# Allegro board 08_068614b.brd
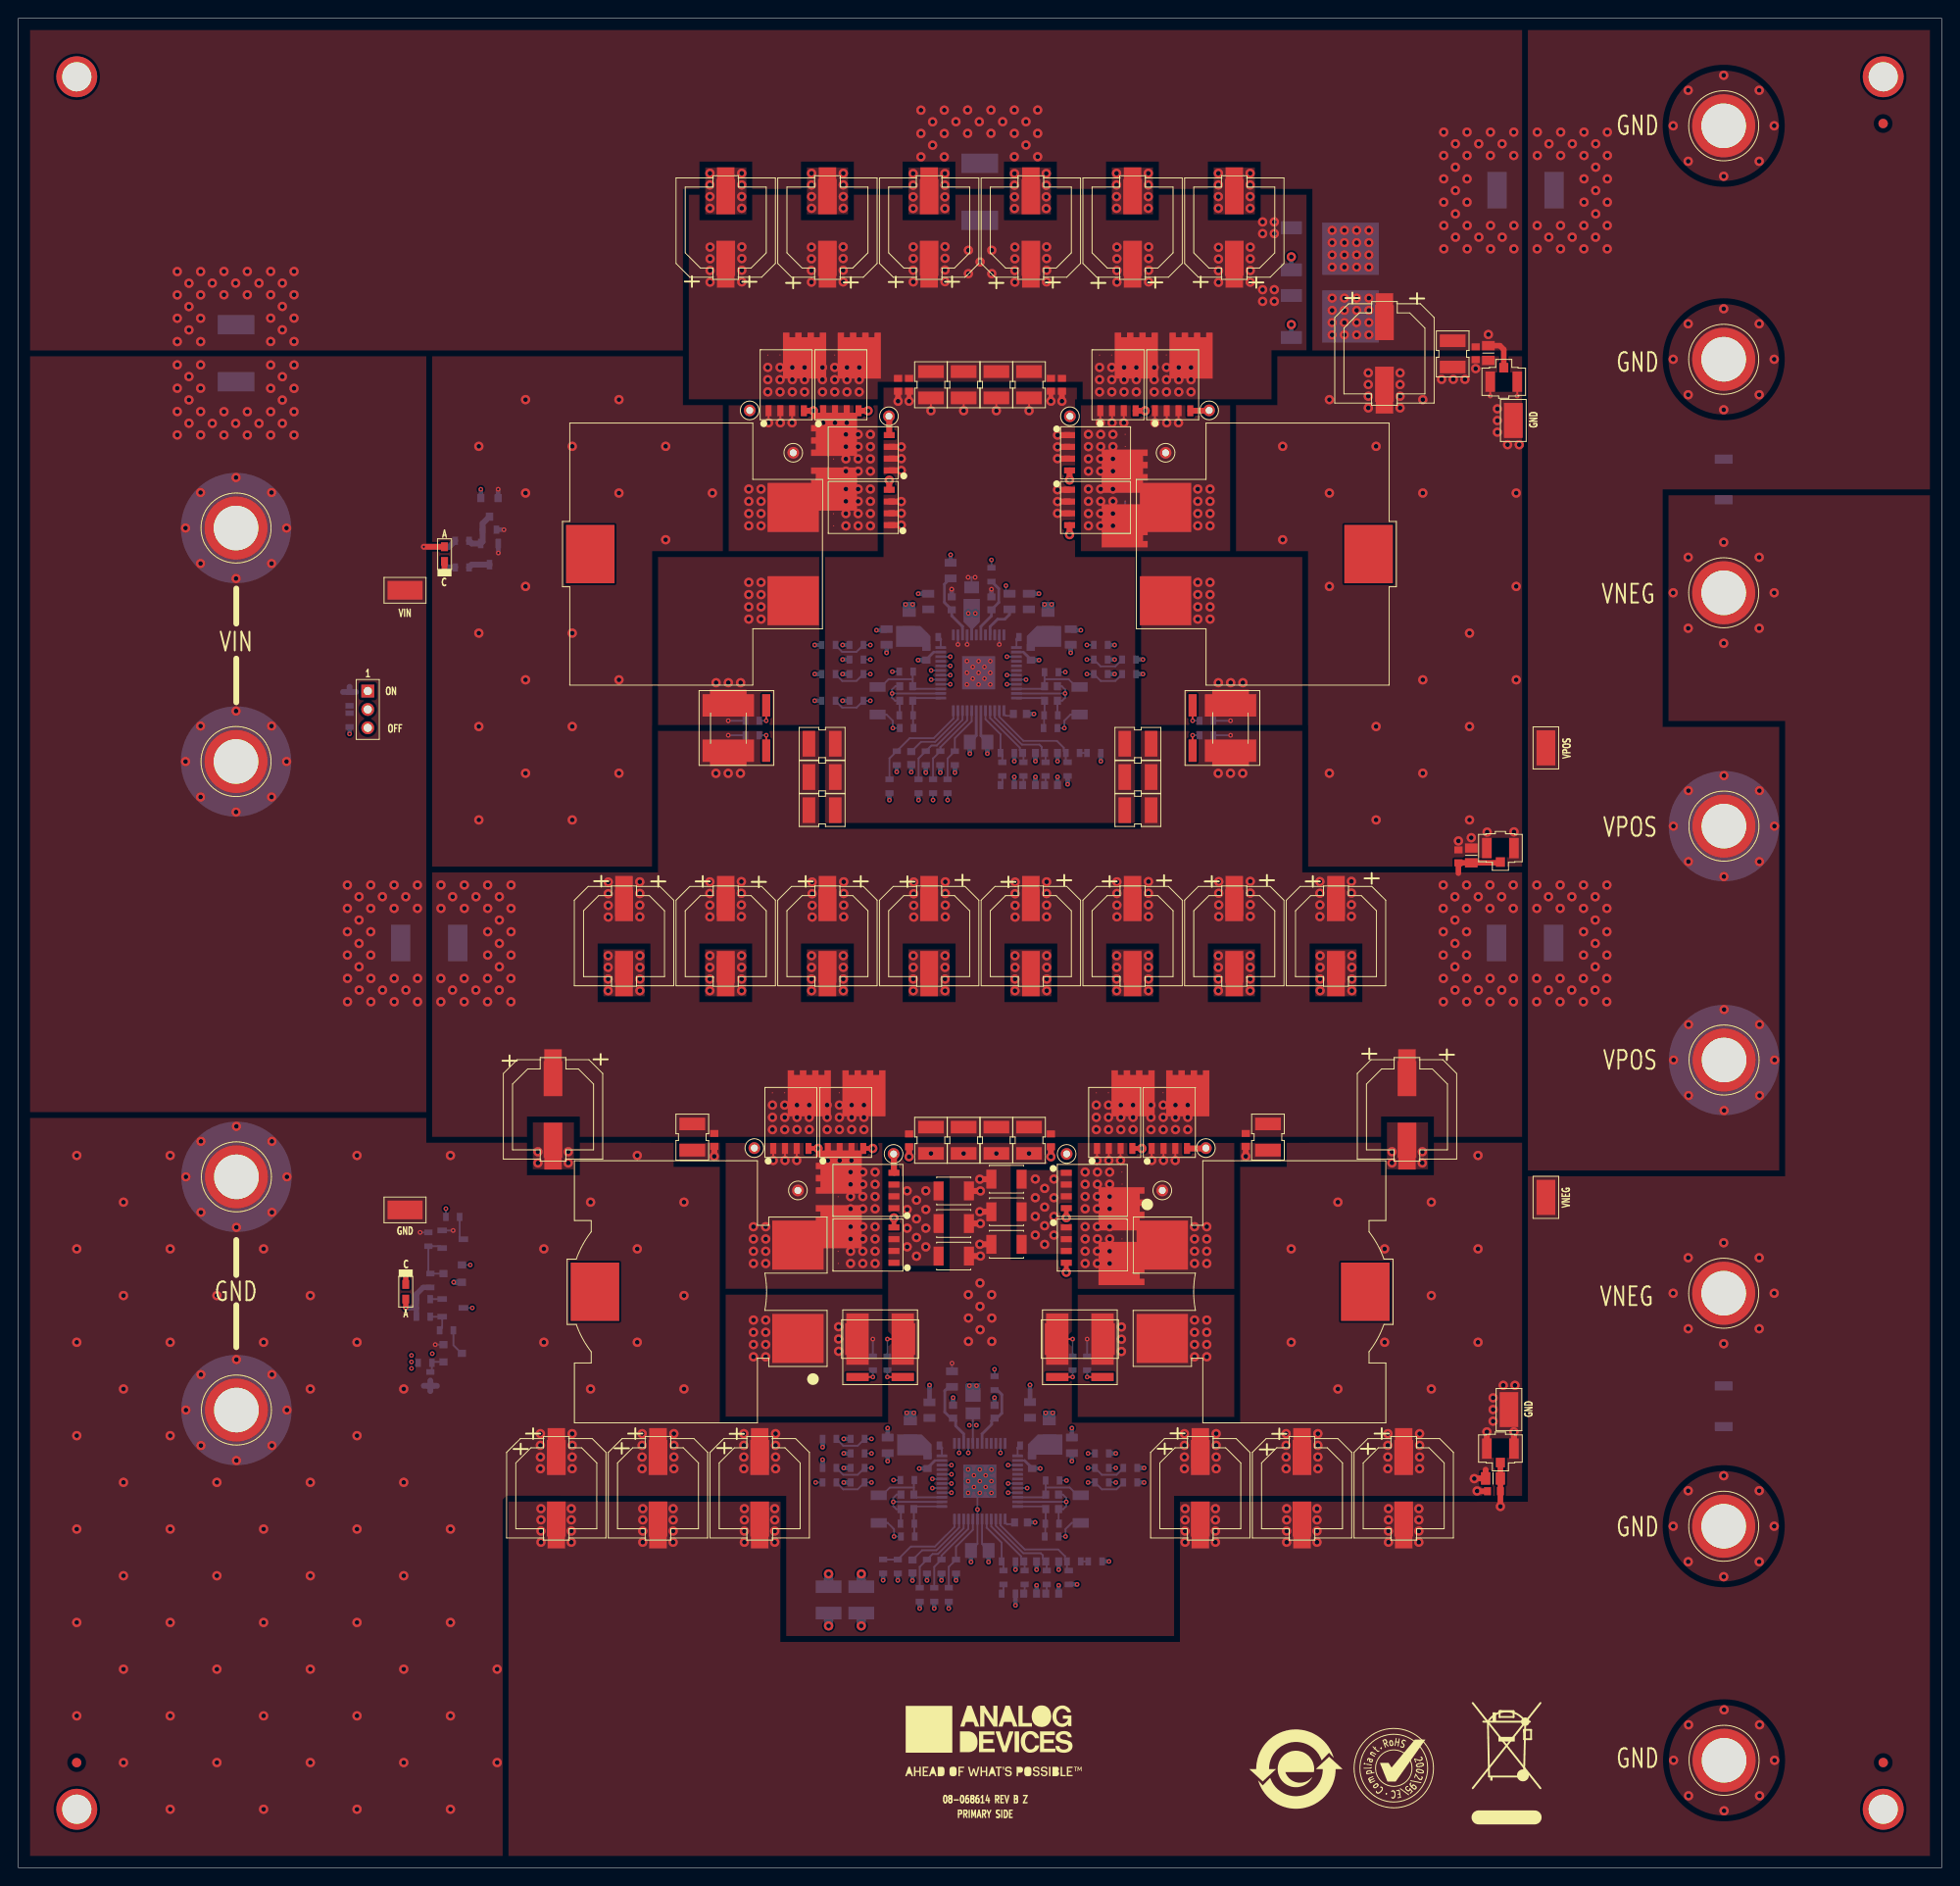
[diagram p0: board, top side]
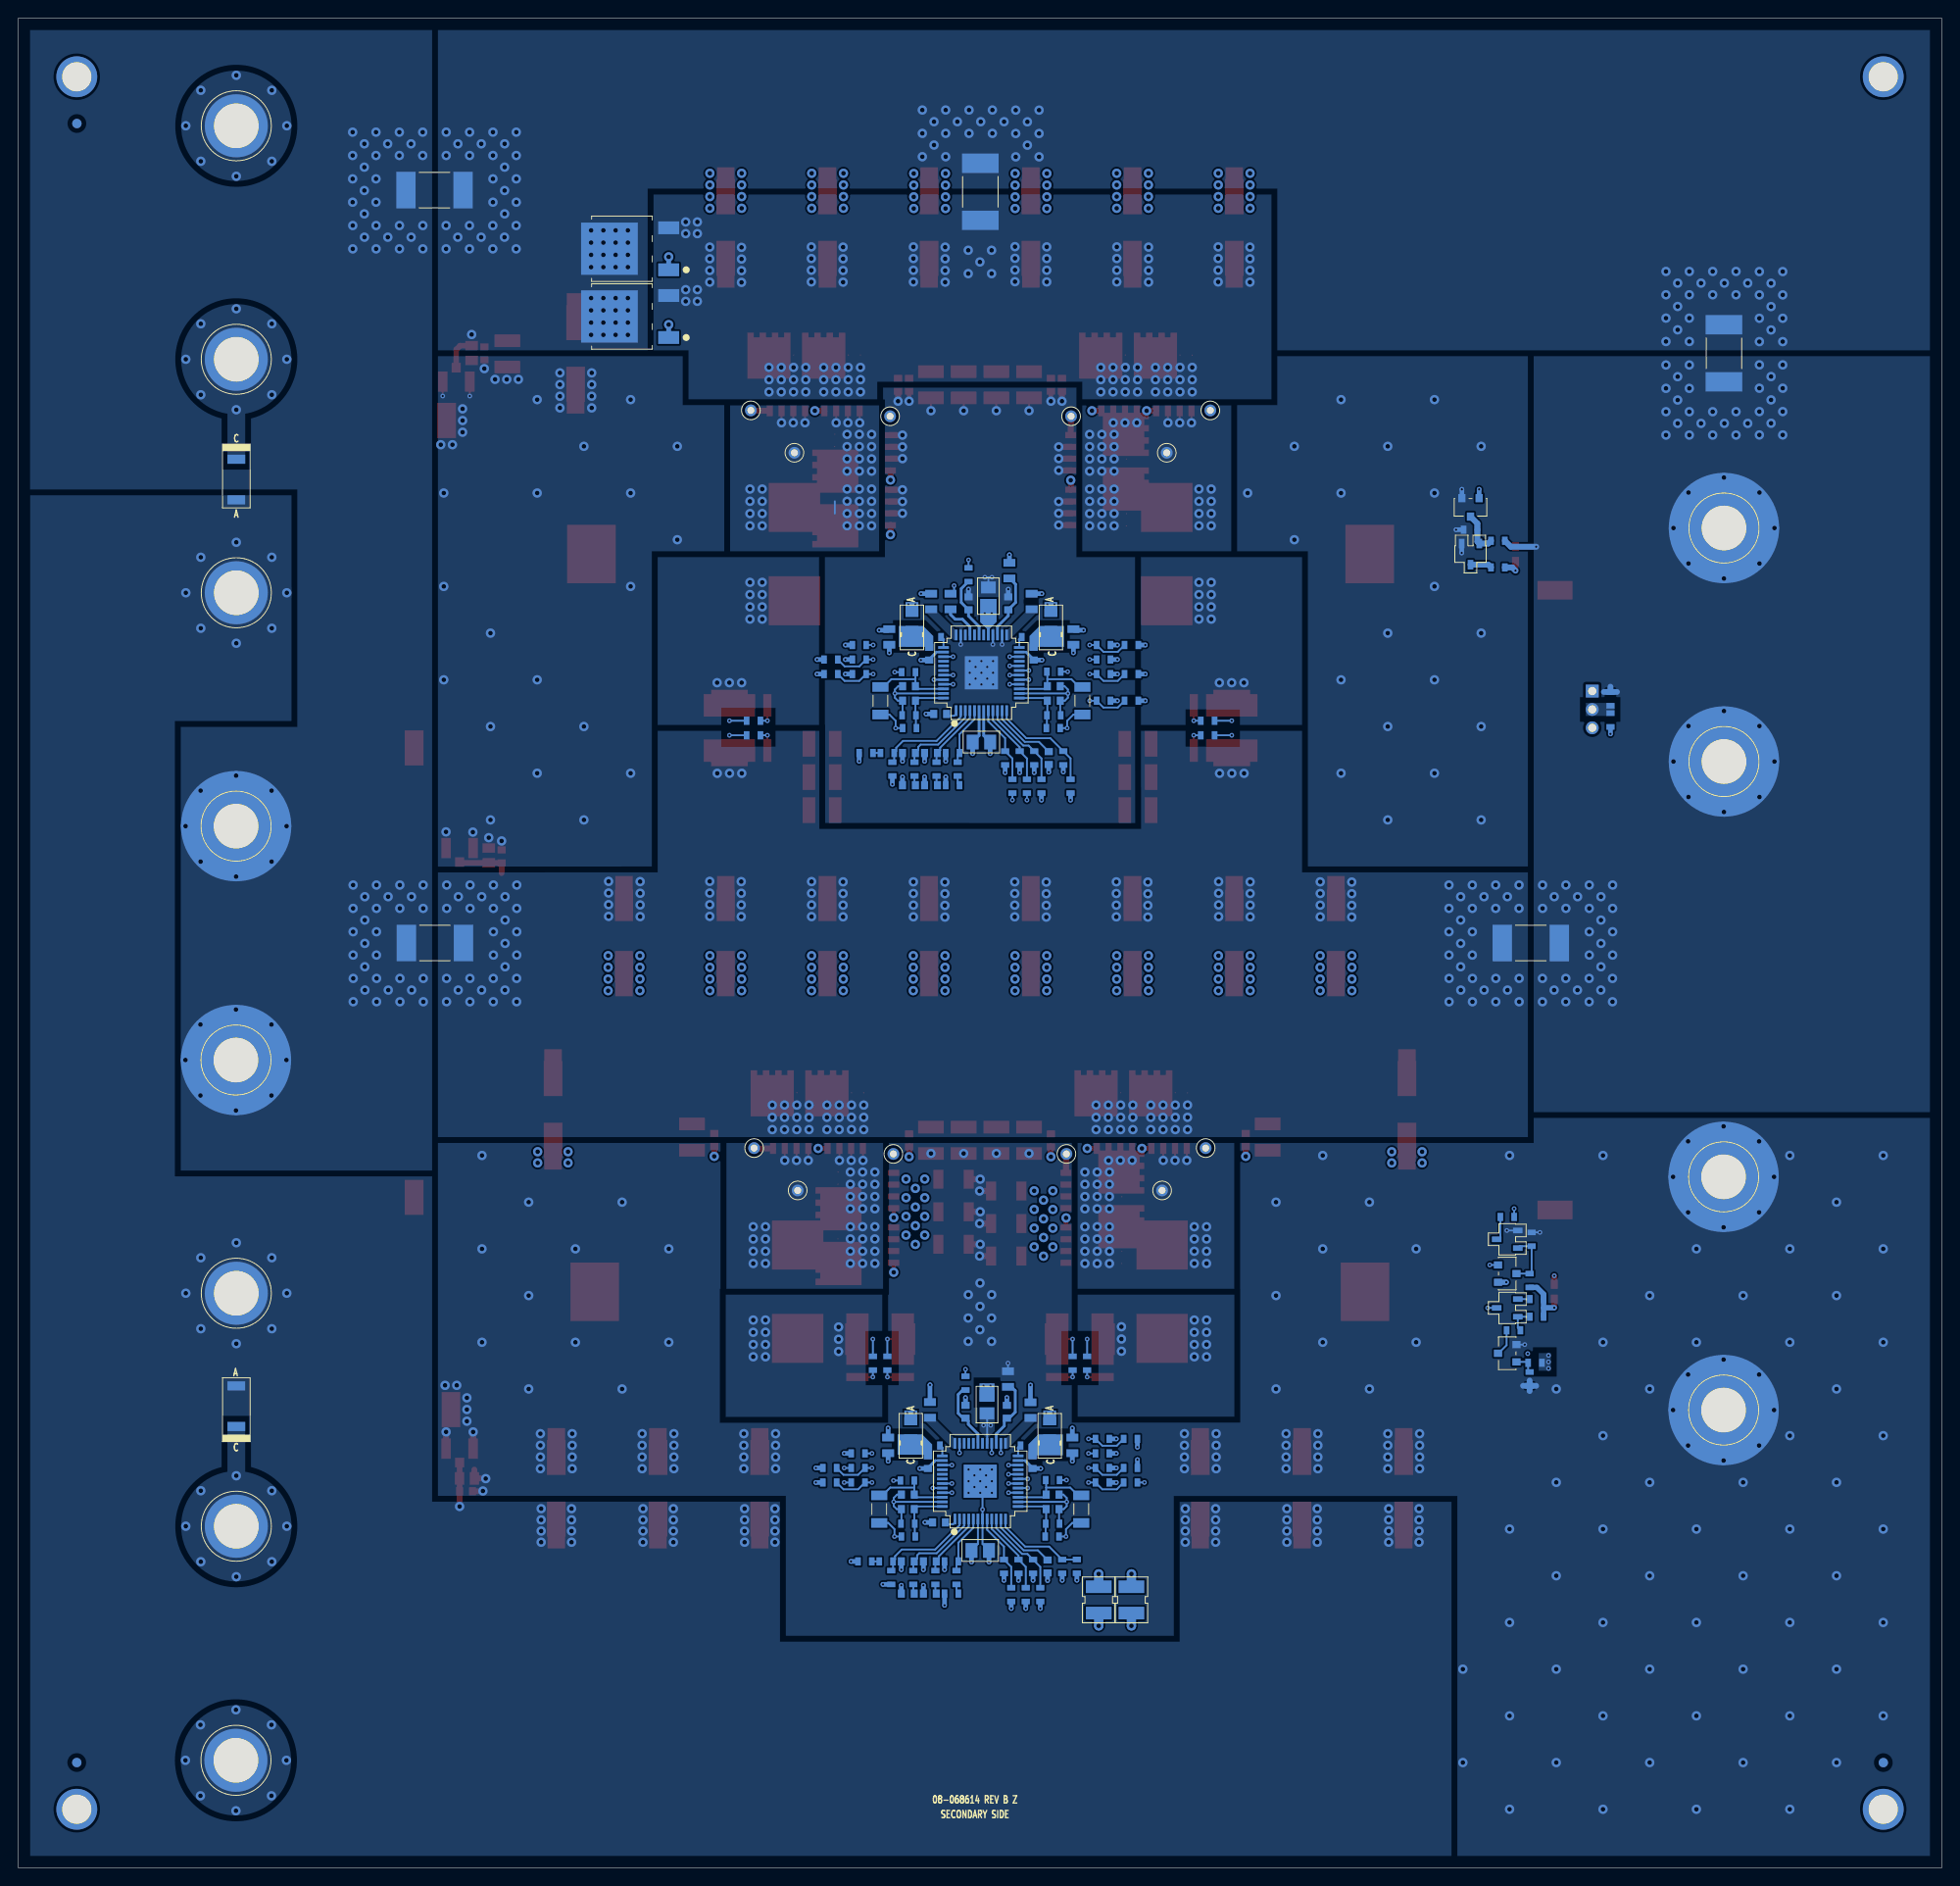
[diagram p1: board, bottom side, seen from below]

Outline 209.17 x 201.17 mm; copper layers: TOP, L2_PWR, L3_SIG, L4_SIG, L5_GND, BOTTOM. Coordinates in mm from the lower left corner of the outline.
Outline path: 0,201.17 0,0 209.17,0 209.17,201.17 0,201.17

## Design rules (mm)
constraint set DEFAULT: 

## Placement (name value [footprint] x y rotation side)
C1  0.1NF  [C0603]  109.91 121.25 0 bottom
C2  0.1uF  [C0603]  109.91 117.75 0 bottom
C3  47PF  [C0603]  112.31 121.25 0 bottom
C4  0.01uF  [C0603]  112.31 117.75 0 bottom
C5  10pF  [C0603]  97.11 120.7 90 bottom
C6  0.01uF  [C0603]  108.92 125.5 180 bottom
C7  4.7uF  [C0805H53]  103.67 138.31 270 bottom
C8  4.7uF  [C0805H53]  104.43 122.44 180 bottom
C9  0.1uF  [C0603]  105.83 137.53 270 bottom
C10  0.22uF  [C0603]  110.12 132.06 90 bottom
C11  0.22uF  [C0603]  98.75 132.06 90 bottom
C12  1uF  [C0603]  101.51 137.53 90 bottom
C13  120UF  [CPLSMSQ406H500]  99.05 178.42 90 top
C14  120UF  [CPLSMSQ406H500]  87.99 178.42 90 top
C15  120UF  [CPLSMSQ406H500]  110.12 178.42 90 top
C16  0.1uF  [C0603]  96.87 161.31 270 top
C17  120UF  [CPLSMSQ406H500]  121.18 178.42 90 top
C18  10UF  [C1210H110]  99.25 161.31 90 top
C19  0.1uF  [C0603]  112.3 161.31 270 top
C20  10UF  [C1210H110]  102.81 161.31 90 top
C21  0.1uF  [C0603]  95.67 161.31 90 top
C22  10UF  [C1210H110]  106.36 161.31 90 top
C23  10UF  [C1210H110]  109.92 161.31 90 top
C24  0.1uF  [C0603]  113.5 161.31 90 top
C25  0.1uF  [C0603]  96.56 126.94 0 bottom
C26  0.1uF  [C0603]  112.3 126.94 180 bottom
C27  0.1uF  [C0603]  96.56 128.52 0 bottom
C28  120UF  [CPLSMSQ406H500]  99.05 101.33 270 top
C29  0.1uF  [C0603]  112.3 128.52 180 bottom
C30  120UF  [CPLSMSQ406H500]  76.93 101.33 270 top
C31  120UF  [CPLSMSQ406H500]  121.18 101.33 270 top
C32  120UF  [CPLSMSQ406H500]  132.24 101.33 270 top
C33  120UF  [CPLSMSQ406H500]  143.3 101.33 270 top
C34  120UF  [CPLSMSQ406H500]  110.12 101.33 270 top
C35  120UF  [CPLSMSQ406H500]  65.87 101.33 270 top
C36  10UF  [C1210H110]  121.76 118.64 0 top
C37  10UF  [C1210H110]  87.41 122.26 180 top
C38  120UF  [CPLSMSQ406H500]  87.99 101.33 270 top
C39  0.015uF  [C0603]  156.62 110.01 270 top
C40  10UF  [C1210H110]  121.76 115.04 0 top
C41  10UF  [C1210H110]  87.41 118.64 180 top
C42  10UF  [C1210H110]  87.41 115.04 180 top
C43  120UF  [CPLSMSQ406H500]  148.57 164.72 270 top
C44  10UF  [C1210H110]  121.76 122.26 0 top
C45  0.1NF  [C0603]  110.04 33.31 0 bottom
C46  0.1uF  [C0603]  110.04 29.81 0 bottom
C47  33pF  [C0603]  112.44 33.31 0 bottom
C48  0.015uF  [C0603]  112.44 29.81 0 bottom
C49  10pF  [C0603]  97.24 32.76 90 bottom
C50  0.01uF  [C0603]  109.04 37.56 180 bottom
C51  4.7uF  [C0805H53]  103.82 50.37 270 bottom
C52  4.7uF  [C0805H53]  104.56 34.5 180 bottom
C53  0.1uF  [C0603]  106.16 49.59 270 bottom
C54  0.22uF  [C0603]  110.24 44.12 90 bottom
C55  0.22uF  [C0603]  98.88 44.12 90 bottom
C56  1uF  [C0603]  101.66 49.59 90 bottom
C57  100UF  [CPLSMSQ327H276]  65.87 101.33 270 top
C58  100UF  [CPLSMSQ327H276]  76.93 101.33 270 top
C59  100UF  [CPLSMSQ327H276]  87.99 101.33 270 top
C60  0.1uF  [C0603]  96.87 79.12 270 top
C61  100UF  [CPLSMSQ327H276]  99.05 101.33 270 top
C62  10UF  [C1210H110]  102.81 79.12 90 top
C63  0.1uF  [C0603]  133.49 79.16 270 top
C64  10UF  [C1210H110]  99.25 79.12 90 top
C65  0.1uF  [C0603]  75.68 79.16 90 top
C66  68UF  [CPLSMSQ406H500]  151.02 82.48 270 top
C67  0.1uF  [C0603]  112.3 79.12 90 top
C68  10UF  [C1210H110]  73.29 79.47 90 top
C69  0.47uF  [C0603]  96.69 39 0 bottom
C70  10UF  [C1210H110]  88.12 29.12 270 bottom
C71  0.47uF  [C0603]  112.43 39 180 bottom
C72  100UF  [CPLSMSQ327H276]  110.12 101.33 270 top
C73  100UF  [CPLSMSQ327H276]  121.18 101.33 270 top
C74  0.1uF  [C0603]  96.69 40.58 0 bottom
C75  100UF  [CPLSMSQ327H276]  132.24 101.33 270 top
C76  100UF  [CPLSMSQ327H276]  143.3 101.33 270 top
C77  0.1uF  [C0603]  112.43 40.58 180 bottom
C78  330UF  [CPLSMSQ406H500]  69.56 41.27 270 top
C79  330UF  [CPLSMSQ406H500]  80.63 41.27 270 top
C80  10UF  [C1210H110]  106.36 79.12 90 top
C81  330UF  [CPLSMSQ406H500]  58.5 41.27 270 top
C82  10UF  [C1210H110]  109.92 79.12 90 top
C83  330UF  [CPLSMSQ406H500]  150.67 41.27 270 top
C84  10uF  [C1210H106]  101.73 73.61 0 top
C85  330UF  [CPLSMSQ406H500]  139.61 41.27 270 top
C86  10uF  [C1210H106]  101.73 70.07 0 top
C87  68UF  [CPLSMSQ406H500]  58.15 82.48 270 top
C88  330UF  [CPLSMSQ406H500]  128.54 41.27 270 top
C89  10uF  [C1210H106]  101.73 66.53 0 top
C90  10uF  [C1210H106]  107.47 67.81 180 top
C91  10UF  [C1210H110]  135.9 79.47 90 top
C92  0.1uF  [C0603]  158.49 164.74 90 top
C93  10uF  [C1210H106]  107.47 71.35 180 top
C94  10UF  [C1210H110]  91.67 29.12 270 bottom
C95  10uF  [C1210H106]  107.47 74.89 180 top
C96  0.015uF  [C0603]  160.48 40.94 180 top
C97  120UF  [CPLSMSQ406H500]  76.93 178.42 90 top
C98  68UF  [CPLSMSQ327H461]  58.5 41.27 270 top
C99  120UF  [CPLSMSQ406H500]  132.24 178.42 90 top
C100  68UF  [CPLSMSQ327H461]  69.56 41.27 270 top
C101  68UF  [CPLSMSQ327H461]  58.15 82.48 270 top
C102  68UF  [CPLSMSQ327H461]  76.93 178.42 90 top
C103  68UF  [CPLSMSQ327H461]  151.02 82.48 270 top
C104  68UF  [CPLSMSQ327H461]  128.54 41.27 270 top
C105  68UF  [CPLSMSQ327H461]  87.99 178.42 90 top
C106  68UF  [CPLSMSQ327H461]  99.05 178.42 90 top
C107  68UF  [CPLSMSQ327H461]  139.61 41.27 270 top
C108  68UF  [CPLSMSQ327H461]  110.12 178.42 90 top
C109  68UF  [CPLSMSQ327H461]  150.67 41.27 270 top
C110  68UF  [CPLSMSQ327H461]  121.18 178.42 90 top
C111  68UF  [CPLSMSQ327H461]  80.63 41.27 270 top
C112  68UF  [CPLSMSQ327H461]  132.24 178.42 90 top
C113  68UF  [CPLSMSQ327H461]  148.57 164.72 270 top
C114  10UF  [C1210H110]  155.99 164.67 90 top
C115  0.015uF  [C0805]  159.87 164.76 90 top
C116  0.015uF  [C0805]  158.01 110.11 270 top
C117  0.015uF  [C0805]  160.38 42.34 180 top
D1  DFLS1100-7  [POWERDI123]  111.99 134.91 90 bottom
D2  DFLS1100-7  [POWERDI123]  96.88 134.91 90 bottom
D3  DFLS1100-7  [POWERDI123]  112.11 46.97 90 bottom
D4  DFLS1100-7  [POWERDI123]  97 46.97 90 bottom
D5  PMEG3050EP,115  [SOD128]  185.47 50.19 90 bottom
D6  PMEG3050EP,115  [SOD128]  185.47 151 270 bottom
DS1  TLMS1000GS08  [LED0603]  46.34 142.89 90 top
DS2  TLMS1000GS08  [LED0603]  42.13 62.64 270 top
J1  U.FL-R-SMT-1(01)  [CNHIROSE-U_FL-R-SMT-1]  161.55 161.65 180 top
J2  U.FL-R-SMT-1(01)  [CNHIROSE-U_FL-R-SMT-1]  161.18 110.91 0 top
J3  U.FL-R-SMT-1(01)  [CNHIROSE-U_FL-R-SMT-1]  161.18 45.59 0 top
L1  2.2UH  [L2815]  69.92 142.89 90 top
L2  2.2UH  [L2815]  139.12 142.89 270 top
L3  6.8UH  [LSML1102W764H728]  73.22 62.64 90 top
L4  6.8UH  [LSML1102W764H728]  135.97 62.65 270 top
NOREF  -  []  104.65 96.77 0 top
NOREF#2  -  []  171.13 21.59 0 top
NOREF#3  -  []  85.65 7.39 0 top
NOREF#4  -  []  138.94 10.72 0 top
NOREF#5  -  []  209.17 0 90 top
NOREF#6  -  []  0 201.17 0 top
NOREF#7  -  []  205.61 6.35 0 top
NOREF#8  -  []  10.82 307.1 0 top
NOREF#9  -  []  43.39 83.91 0 top
NOREF#10  -  []  104.83 225.4 0 top
NOREF#11  -  []  -50.8 -58.06 0 top
NOREF#12  -  []  0 0 0 top
NOREF#13  -  []  249 269.2 0 top
NOREF#14  -  []  188.64 37.14 0 top
NOREF#15  -  []  -50.8 -58.06 0 top
NOREF#16  -  []  209.17 0 90 top
NOREF#17  -  [unnamed#2]  6.35 6.35 0 top
NOREF#18  -  [unnamed#2]  6.35 194.82 0 top
NOREF#19  -  []  -50.8 -58.06 0 top
NOREF#20  -  []  9.07 14.72 0 top
NOREF#21  -  []  9.07 14.72 0 top
NOREF#22  -  []  149.59 10.82 0 top
NOREF#23  -  []  0 201.17 270 top
NOREF#24  -  []  106.07 13.77 0 top
NOREF#25  -  []  6.35 6.35 0 top
NOREF#26  -  []  -50.8 -58.06 0 top
NOREF#27  -  []  6.35 6.35 0 top
NOREF#28  -  [unnamed#2]  202.82 194.82 0 top
NOREF#29  -  []  0 0 0 top
NOREF#30  -  []  209.17 0 0 top
NOREF#31  -  [unnamed#2]  6.34 11.42 0 top
NOREF#32  -  [unnamed#2]  202.82 6.35 0 top
NOREF#33  -  []  209.17 201.17 180 top
NOREF#34  -  []  0 201.17 0 top
NOREF#35  -  [unnamed#2]  202.81 189.73 0 top
NOREF#36  -  []  0 0 0 top
NOREF#37  -  []  274.23 90.82 0 top
NOREF#38  -  [unnamed#2]  202.82 11.43 0 top
NOREF#39  -  [unnamed#2]  6.34 11.42 180 bottom
NOREF#40  -  [unnamed#2]  202.82 11.43 180 bottom
NOREF#41  -  [unnamed#2]  202.81 189.73 180 bottom
P1  KFH-032-10ET  [CNPEMKFH-032]  23.67 145.73 0 top
P2  KFH-032-10ET  [CNPEMKFH-032]  23.67 120.33 0 top
P3  KFH-032-10ET  [CNPEMKFH-032]  23.71 49.78 0 top
P4  KFH-032-10ET  [CNPEMKFH-032]  23.71 75.15 0 top
P5  62000311121  [CNTHMHDR1X3L236W79H244]  38 127.99 270 top
P6  KFH-032-10ET  [CNPEMKFH-032]  185.51 87.85 0 top
P7  KFH-032-10ET  [CNPEMKFH-032]  185.51 11.67 0 top
P8  KFH-032-10ET  [CNPEMKFH-032]  185.49 113.3 0 top
P9  KFH-032-10ET  [CNPEMKFH-032]  185.47 189.48 0 top
P12  KFH-032-10ET  [CNPEMKFH-032]  185.47 37.14 0 top
P13  KFH-032-10ET  [CNPEMKFH-032]  185.47 62.48 0 top
P14  KFH-032-10ET  [CNPEMKFH-032]  185.47 164.08 0 top
P15  KFH-032-10ET  [CNPEMKFH-032]  185.47 138.68 0 top
Q1  2N7002LT1G  [SOT23-M3]  51.24 147.97 0 bottom
Q2  SUD50P08-25L  [TO252-3]  142.64 168.74 90 bottom
Q3  SUD50P08-25L  [TO252-3]  142.64 176.11 90 bottom
Q4  DMN67D8L-7  [SOT23_B]  51.24 142.89 0 bottom
Q5  BSC032N04LSATMA1  [SON8]  83.51 161.31 0 top
Q6  BSC032N04LSATMA1  [SON8]  91.89 147.97 90 top
Q7  BSC032N04LSATMA1  [SON8]  119.59 161.31 0 top
Q8  BSC032N04LSATMA1  [SON8]  117.15 153.91 270 top
Q9  BSC032N04LSATMA1  [SON8]  89.45 161.31 0 top
Q10  BSC032N04LSATMA1  [SON8]  91.89 153.91 90 top
Q11  BSC032N04LSATMA1  [SON8]  125.54 161.31 0 top
Q12  BSC032N04LSATMA1  [SON8]  117.15 147.97 270 top
Q13  2N7002LT1G  [SOT23-M3]  47.24 55.95 90 bottom
Q14  DMP610DL  [SOT23_B]  47.24 60.89 90 bottom
Q15  2N7002LT1G  [SOT23-M3]  47.24 64.62 270 bottom
Q16  DMN67D8L-7  [SOT23_B]  47.24 68.35 90 bottom
Q17  BSC065N06LS5ATMA1  [SON8]  89.96 81.06 0 top
Q18  BSC027N06LS5ATMA1  [SON8]  92.4 73.67 90 top
Q19  BSC065N06LS5ATMA1  [SON8]  119.23 81.06 0 top
Q20  BSC027N06LS5ATMA1  [SON8]  116.8 67.72 270 top
Q21  BSC065N06LS5ATMA1  [SON8]  84.01 81.06 0 top
Q22  BSC027N06LS5ATMA1  [SON8]  92.4 67.72 90 top
Q23  BSC065N06LS5ATMA1  [SON8]  125.18 81.06 0 top
Q24  BSC027N06LS5ATMA1  [SON8]  116.8 73.67 270 top
R1  0.0007  [R2726]  78.1 123.97 270 top
R2  0.0007  [R2726]  130.95 123.97 90 top
R3  0.0007  [R2726]  93.72 56.61 180 top
R4  0.0007  [R2726]  115.45 56.61 180 top
R5  4.53K  [R0603]  109.31 119.5 270 bottom
R6  143K  [R0603]  97.9 117.64 90 bottom
R7  0  [R0603]  91.15 129.84 180 bottom
R8  3.32K  [R0603]  111.71 119.5 270 bottom
R9  30.1K  [R0603]  88.12 129.84 0 bottom
R10  9.53K  [R0603]  98.69 120.7 270 bottom
R11  196K  [R0603]  94.74 117.64 90 bottom
R12  53.6K  [R0603]  95.53 120.7 90 bottom
R13  0  [R0603]  117.72 131.42 180 bottom
R14  0  [R0603]  120.8 131.42 180 bottom
R15  0  [R0603]  117.72 129.84 180 bottom
R16  0  [R0603]  120.8 129.84 0 bottom
R17  90.9K  [R0603]  99.48 117.64 270 bottom
R18  5.9K  [R0603]  100.27 120.7 270 bottom
R19  71.5K  [R0603]  117.72 133 180 bottom
R20  100K  [R0603]  101.06 117.64 270 bottom
R21  4.42K  [R0603]  101.85 120.7 270 bottom
R22  0  [R0603]  91.15 133 0 bottom
R23  0  [R0603]  88.12 133 180 bottom
R24  100K  [R0603]  91.15 131.42 0 bottom
R25  0  [R0603]  91.15 126.94 0 bottom
R26  0  [R2512H35]  104.55 182.3 270 bottom
R27  0  [R0805]  107.79 137.73 270 bottom
R28  1MEG  [R0603]  48.26 144.34 0 bottom
R29  1MEG  [R0603]  51.24 145.54 0 bottom
R30  11.3K  [R0603]  48.26 141.44 0 bottom
R31  2.2  [R0603]  105.83 140.65 90 bottom
R32  0  [R0805]  114.45 133.88 90 bottom
R33  0  [R0805]  109.9 137.73 90 bottom
R34  0  [R0805]  94.43 133.88 90 bottom
R35  0  [R0805]  98.97 137.73 90 bottom
R36  0  [R0805]  101.39 141.09 90 bottom
R37  10  [R0603]  107.56 117.75 180 bottom
R38  499K  [R0603]  107.01 119.5 90 bottom
R39  26.1K  [R0603]  107.56 121.25 0 bottom
R40  10  [R0603]  116.98 121.25 0 bottom
R41  90.9K  [R0603]  114.66 121.25 180 bottom
R42  6.65K  [R0603]  114.11 119.5 270 bottom
R43  6.81K  [R0603]  96.62 123.96 0 bottom
R44  680  [R0603]  96.56 125.36 0 bottom
R45  0  [R1206]  93.45 126.94 90 bottom
R46  6.81K  [R0603]  112.25 123.96 180 bottom
R47  0  [R0603]  96.56 130.1 180 bottom
R48  0  [R0603]  79.82 124.76 180 bottom
R49  680  [R0603]  112.3 125.36 180 bottom
R50  0  [R1206]  115.42 126.94 90 bottom
R51  0.0008  [R2512H35]  77.21 123.97 270 top
R52  0  [R0603]  112.35 130.05 0 bottom
R53  0  [R0603]  129.22 124.76 0 bottom
R54  0  [R0603]  79.82 123.18 180 bottom
R55  0.0008  [R2512H35]  131.84 123.97 270 top
R56  0  [R0603]  129.22 123.18 0 bottom
R57  10.7  [R0603]  99.3 133.86 180 bottom
R58  4.53K  [R0603]  109.44 31.56 270 bottom
R59  1MEG  [R0603]  44.04 59.93 0 bottom
R60  1MEG  [R0603]  46.56 58.46 0 bottom
R61  0  [R0603]  88.21 43.48 180 bottom
R62  10K  [R0603]  111.84 31.56 270 bottom
R63  30.1K  [R0603]  91.27 43.48 0 bottom
R64  1.24MEG  [R0603]  98.03 29.7 90 bottom
R65  100K  [R0603]  44.04 61.84 0 bottom
R66  100K  [R0603]  88.21 41.9 0 bottom
R67  20K  [R0603]  91.27 41.9 180 bottom
R68  200K  [R0603]  94.05 32.77 90 bottom
R69  82.5K  [R0603]  98.82 32.76 270 bottom
R70  0  [R0603]  117.84 43.48 180 bottom
R71  0  [R0603]  120.93 43.48 180 bottom
R72  0  [R0603]  117.84 41.9 180 bottom
R73  95.3K  [R0603]  95.64 32.76 270 bottom
R74  0  [R0603]  120.93 41.9 0 bottom
R75  1.24MEG  [R0603]  99.61 29.7 270 bottom
R76  110K  [R0603]  100.4 32.76 270 bottom
R77  49.9K  [R0603]  117.84 45.06 0 bottom
R78  0  [R0603]  88.21 46.64 0 bottom
R79  0  [R0603]  91.27 46.64 180 bottom
R80  196K  [R0603]  101.19 29.7 270 bottom
R81  18.2K  [R0603]  101.98 32.76 270 bottom
R82  100K  [R0603]  91.27 45.06 0 bottom
R83  100K  [R0603]  44.81 63.87 90 bottom
R84  100K  [R0603]  44.59 68.35 90 bottom
R85  11.3K  [R0603]  47.24 70.78 0 bottom
R86  2.2  [R0603]  106.16 52.7 90 bottom
R87  0  [R0805]  114.58 45.94 90 bottom
R88  0  [R0805]  110.03 49.79 90 bottom
R89  0  [R0805]  94.54 45.94 90 bottom
R90  0  [R0805]  99.09 49.77 90 bottom
R91  0  [R0805]  101.54 53.15 90 bottom
R92  10  [R0603]  107.69 29.81 180 bottom
R93  1.24MEG  [R0603]  107.14 31.56 90 bottom
R94  42.2K  [R0603]  107.69 33.31 0 bottom
R95  10  [R0603]  117.1 33.31 0 bottom
R96  90.9K  [R0603]  114.79 33.31 180 bottom
R97  6.65K  [R0603]  114.24 31.56 270 bottom
R98  7.32K  [R0603]  96.74 36.02 0 bottom
R99  732  [R0603]  96.69 37.42 0 bottom
R100  0  [R1206]  93.57 39 90 bottom
R101  7.32K  [R0603]  112.38 36.02 180 bottom
R102  0  [R0603]  96.69 42.16 180 bottom
R103  0  [R0603]  92.94 54.87 90 bottom
R104  732  [R0603]  112.43 37.42 180 bottom
R105  0  [R1206]  115.54 39 90 bottom
R106  0.002  [R2512H57]  93.72 57.5 180 top
R107  0  [R0603]  112.48 42.11 0 bottom
R108  0  [R0603]  116.23 54.87 90 bottom
R109  0  [R0603]  94.51 54.87 90 bottom
R110  0.002  [R2512H57]  115.45 57.5 180 top
R111  0  [R0603]  114.66 54.87 90 bottom
R112  0  [R2512H35]  23.67 164.74 90 bottom
R113  0  [R2512H35]  44.68 100.58 0 bottom
R114  0  [R2512H35]  163.87 100.58 0 bottom
R115  0  [R2512H35]  163.92 182.49 0 bottom
R116  0  [R0603]  88.12 126.94 180 bottom
R117  150K  [R0603]  36.02 127.14 270 bottom
R118  10K  [R0603]  36.02 124.84 270 bottom
R119  10.7  [R0603]  109.57 133.86 0 bottom
R120  10K  [R0603]  44.22 54.91 0 bottom
R121  10K  [R0603]  44.81 53.16 270 bottom
R122  2  [R0603]  99.43 45.92 180 bottom
R123  2  [R0603]  109.69 45.92 0 bottom
TP1  5019  [CNKEY5019]  42.05 138.96 0 top
TP2  5019  [CNKEY5019]  42.05 71.54 0 top
TP3  TESTPAD  [TPC50D30]  84.27 153.91 0 top
TP4  TESTPAD  [TPC50D30]  79.53 158.52 0 top
TP5  TESTPAD  [TPC50D30]  94.68 157.89 0 top
TP6  TESTPAD  [TPC50D30]  124.77 153.91 0 top
TP7  TESTPAD  [TPC50D30]  129.51 158.53 90 top
TP8  TESTPAD  [TPC50D30]  114.36 157.89 0 top
TP9  5019  [CNKEY5019]  166.13 121.81 90 top
TP10  5019  [CNKEY5019]  162.59 157.43 270 top
TP11  TESTPAD  [TPC50D30]  84.78 73.67 0 top
TP12  TESTPAD  [TPC50D30]  80.04 78.27 90 top
TP13  TESTPAD  [TPC50D30]  95.19 77.64 0 top
TP14  TESTPAD  [TPC50D30]  124.41 73.67 0 top
TP15  TESTPAD  [TPC50D30]  129.15 78.27 270 top
TP16  TESTPAD  [TPC50D30]  114.01 77.64 0 top
TP17  5019  [CNKEY5019]  162.12 49.83 270 top
TP18  5019  [CNKEY5019]  166.13 72.92 90 top
U1  LTC3871ILXE#PBF  [LQFP48_7X7_PAD3_6X3_6]  104.43 129.98 180 bottom
U2  LTC3871ILXE#PBF  [LQFP48_7X7_PAD3_6X3_6]  104.56 42.04 180 bottom

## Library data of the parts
C1 C45 = CAP: User Part Number: UPN; Tolerance: 10; alternate symbols: (C0603L); part number: CAP_SM-0.1NF,100V,10,E043558,C0603; tolerance: 10
C2 C46 = CAP: User Part Number: UPN; Tolerance: 10; alternate symbols: (C0603L); part number: CAP_SM-0.1UF,50V,10,E011865,C0603; tolerance: 10
C3 = CAP: User Part Number: UPN; Tolerance: 10; alternate symbols: (C0603L); part number: CAP_SM-47PF,50V,10,E043593,C0603; tolerance: 10
C4 = CAP: User Part Number: UPN; Tolerance: 10; alternate symbols: (C0603L); part number: CAP_SM-0.01UF,100V,10,E032297,C0603; tolerance: 10
C5 C49 = CAP: User Part Number: UPN; Tolerance: 1; alternate symbols: (C0603L); part number: CAP_SM-10PF,25V,1,E039157,C0603; tolerance: 1
C6 C50 = CAP: User Part Number: UPN; Tolerance: 10; alternate symbols: (C0603L); part number: CAP_SM-0.01UF,50V,10,E000421,C0603; tolerance: 10
C7 C8 C51 C52 = CAP: Tolerance: 10; User Part Number: UPN; alternate symbols: (C0805H53); part number: CAP_SM-4.7UF,16V,10,E031879,C0805H53; tolerance: 10
C9 C53 = CAP: User Part Number: UPN; Tolerance: 10; alternate symbols: (C0603L); part number: CAP_SM-0.1UF,50V,10,E014757,C0603; tolerance: 10
C10 C11 C54 C55 = CAP: User Part Number: UPN; Tolerance: 10; alternate symbols: (C0603L); part number: CAP_SM-0.22UF,50V,10,E015565,C0603; tolerance: 10
C12 C56 = CAP: User Part Number: UPN; Tolerance: 10; alternate symbols: (C0603L); part number: CAP_SM-1UF,50V,10,E023087,C0603; tolerance: 10
C13-C15 C17 C28 C30-C35 C38 C43 C97 C99 = CAPP: Tolerance: 20; User Part Number: UPN; alternate symbols: (CPLSMSQ406H500); part number: CAPP_SM-120UF,35V,20,E054055,CPLSMSQ406H500; tolerance: 20
C16 C19 C21 C24 C60 C63 C65 C67 C92 = CAP: User Part Number: UPN; Tolerance: 10; alternate symbols: (C0603L); part number: CAP_SM-0.1UF,100V,10,E024908,C0603; tolerance: 10
C18 C20 C22 C23 C36 C37 C40-C42 C44 C62 C64 C68 C70 C80 C82 C91 C94 C114 = CAP: Tolerance: 10; User Part Number: UPN; alternate symbols: (C1210H110); part number: CAP_SM-10UF,75V,10,E054052,C1210H110; tolerance: 10
C25-C27 C29 C74 C77 = CAP: User Part Number: UPN; Tolerance: 10; alternate symbols: (C0603L); part number: CAP_SM-0.1UF,16V,10,E011547,C0603; tolerance: 10
C39 C96 = CAP: User Part Number: UPN; Tolerance: 10; alternate symbols: (C0603L); part number: CAP_SM-0.015UF,25V,10,E000392,C0603; tolerance: 10
C47 = CAP: User Part Number: UPN; Tolerance: 1; alternate symbols: (C0603L); part number: CAP_SM-33PF,100V,1,E032691,C0603; tolerance: 1
C48 = CAP: User Part Number: UPN; Tolerance: 5; alternate symbols: (C0603L); part number: CAP_SM-0.015UF,25V,5,E023542,C0603; tolerance: 5
C57-C59 C61 C72 C73 C75 C76 = CAPP: User Part Number: UPN; Tolerance: 20; alternate symbols: (CPLSMSQ327H276); part number: CAPP_SM-100UF,25V,20,E046046,CPLSMSQ327H276; tolerance: 20
C66 C87 = CAPP: Tolerance: 20; User Part Number: UPN; alternate symbols: (CPLSMSQ406H500); part number: CAPP_SM-68UF,50V,20,E054122,CPLSMSQ406H500; tolerance: 20
C69 C71 = CAP: User Part Number: UPN; Tolerance: 10; alternate symbols: (C0603L); part number: CAP_SM-0.47UF,25V,10,E010966,C0603; tolerance: 10
C78 C79 C81 C83 C85 C88 = CAPP: Tolerance: 20; User Part Number: UPN; alternate symbols: (CPLSMSQ406H500); part number: CAPP_SM-330UF,25V,20,E046016,CPLSMSQ406H500; tolerance: 20
C84 C86 C89 C90 C93 C95 = CAP: Tolerance: 10; User Part Number: UPN; alternate symbols: (C1210H106); part number: CAP_SM-10UF,63V,10,E034035,C1210H106; tolerance: 10
C98 C100-C113 = CAPP: User Part Number: UPN; Tolerance: 20; alternate symbols: (CPLSMSQ327H461); part number: CAPP_SM-68UF,25V,20,E054050,CPLSMSQ327H461; tolerance: 20
C115-C117 = CAP: User Part Number: UPN; Tolerance: 10; alternate symbols: (C0805L); part number: CAP_SM-0.015UF,50V,10,E000449,C0805; tolerance: 10
D1-D4 = DIOSCHOTTKY: User Part Number: UPN; Tolerance: N/A; alternate symbols: (POWERDI123); part number: DIOSCHOTTKY_SM-DFLS1100-7,100V,N/A,E029142,POWERDI123; tolerance: N/A
D5 D6 = DIOSCHOTTKY: User Part Number: UPN; Tolerance: N/A; alternate symbols: (SOD128); part number: DIOSCHOTTKY_SM-PMEG3050EP,115,30V,N/A,E038321,SOD128; tolerance: N/A
DS1 DS2 = DIOLED: Tolerance: N/A; User Part Number: UPN; alternate symbols: (LED0603); part number: DIOLED_SM-TLMS1000GS08,N/A,N/A,E018253,LED0603; tolerance: N/A
J1-J3 = CNBNC3P: Tolerance: N/A; User Part Number: UPN; alternate symbols: (CNHIROSE-U_FL-R-SMT-1); part number: CNBNC3P_SM-U.FL-R-SMT-1(01),E022198,CNHIROSE-U_FL-R-SMT-1; tolerance: N/A
L1 L2 = IND: User Part Number: UPN; Tolerance: 15; alternate symbols: (L2815); part number: IND_SM-2.2UH,15,E043053,L2815; tolerance: 15
L3 L4 = IND: User Part Number: UPN; Tolerance: 20; alternate symbols: (LSML1102W764H728); part number: IND_SM-6.8UH,20,E046412,LSML1102W764H728; tolerance: 20
P1-P4 P6-P9 P12-P15 = CN1P: User Part Number: UPN; Tolerance: N/A; alternate symbols: (CNPEMKFH-032); part number: CN1P_TH-KFH-032-10ET,E039893,CNPEMKFH-032; tolerance: N/A
P5 = CN3P: User Part Number: UPN; Tolerance: N/A; alternate symbols: (CNTHMHDR1X3L236W79H244); part number: CN3P_TH-62000311121,E033291,CNTHMHDR1X3L236W79H244; tolerance: N/A
Q1 Q13 Q15 = TRAN2N7002: User Part Number: UPN; Tolerance: N/A; alternate symbols: (SOT23-M3); part number: TRAN2N7002_SM-2N7002LT1G,E005348,SOT23-M3; tolerance: N/A
Q2 Q3 = TRANPMOSFET_V12: Tolerance: N/A; User Part Number: UPN; alternate symbols: (TO252-3); part number: TRANPMOSFET_V12_SM-SUD50P08-25L,E043648,TO252-3; tolerance: N/A
Q4 Q16 = TRANNMOSFET_V8: User Part Number: UPN; Tolerance: N/A; alternate symbols: (SOT23_B); part number: TRANNMOSFET_V8_SM-DMN67D8L-7,E054426,SOT23_B; tolerance: N/A
Q5-Q12 = TRANNMOSFET_V15: Tolerance: N/A; User Part Number: UPN; alternate symbols: (SON8); part number: TRANNMOSFET_V15_SM-BSC032N04LSATMA1,E043908,SON8; tolerance: N/A
Q14 = TRANPMOSFET_V12: User Part Number: UPN; Tolerance: N/A; alternate symbols: (SOT23_B); part number: TRANPMOSFET_V12_SM-DMP610DL,E054425,SOT23_B; tolerance: N/A
Q17 Q19 Q21 Q23 = TRANNMOSFET_V15: Tolerance: N/A; User Part Number: UPN; alternate symbols: (SON8); part number: TRANNMOSFET_V15_SM-BSC065N06LS5ATMA1,E054054,SON8; tolerance: N/A
Q18 Q20 Q22 Q24 = TRANNMOSFET_V15: Tolerance: N/A; User Part Number: UPN; alternate symbols: (SON8); part number: TRANNMOSFET_V15_SM-BSC027N06LS5ATMA1,E051633,SON8; tolerance: N/A
R1-R4 = RES4PKEL: User Part Number: UPN; Tolerance: 1; alternate symbols: (R2726); part number: RES4PKEL_SM-0.0007,E047247,7W,1,R2726; tolerance: 1
R5 R58 = RES: User Part Number: UPN; Tolerance: 1; alternate symbols: (R0603L); part number: RES_SM-4.53K,E011112,1/10W,1,R0603; tolerance: 1
R6 = RES: User Part Number: UPN; Tolerance: 0.1; alternate symbols: (R0603L); part number: RES_SM-143K,E020916,1/10W,0.1,R0603; tolerance: 0.1
R7 R13-R16 R22 R23 R25 R47 R48 R52-R54 R56 R61 R70-R72 R74 R78 R79 R102 R103 R107-R109 R111 R116 = RES: User Part Number: UPN; Tolerance: JUMPER; alternate symbols: (R0603L); part number: RES_SM-0,E006826,1/10W,JUMPER,R0603; tolerance: JUMPER
R8 = RES: User Part Number: UPN; Tolerance: 1; alternate symbols: (R0603L); part number: RES_SM-3.32K,E042850,1/10W,1,R0603; tolerance: 1
R9 R63 = RES: User Part Number: UPN; Tolerance: 1; alternate symbols: (R0603L); part number: RES_SM-30.1K,E011129,1/10W,1,R0603; tolerance: 1
R10 = RES: User Part Number: UPN; Tolerance: 0.1; alternate symbols: (R0603L); part number: RES_SM-9.53K,E055034,1/10W,0.1,R0603; tolerance: 0.1
R11 R80 = RES: User Part Number: UPN; Tolerance: 0.1; alternate symbols: (R0603L); part number: RES_SM-196K,E023430,1/10W,0.1,R0603; tolerance: 0.1
R12 = RES: User Part Number: UPN; Tolerance: 0.1; alternate symbols: (R0603L); part number: RES_SM-53.6K,E018889,1/10W,0.1,R0603; tolerance: 0.1
R17 R41 R96 = RES: User Part Number: UPN; Tolerance: 0.1; alternate symbols: (R0603L); part number: RES_SM-90.9K,E018389,1/10W,0.1,R0603; tolerance: 0.1
R18 = RES: User Part Number: UPN; Tolerance: 0.1; alternate symbols: (R0603L); part number: RES_SM-5.9K,E024298,1/10W,0.1,R0603; tolerance: 0.1
R19 = RES: User Part Number: UPN; Tolerance: 0.1; alternate symbols: (R0603L); part number: RES_SM-71.5K,E024280,1/10W,0.1,R0603; tolerance: 0.1
R20 = RES: User Part Number: UPN; Tolerance: 0.1; alternate symbols: (R0603L); part number: RES_SM-100K,E018391,1/10W,0.1,R0603; tolerance: 0.1
R21 = RES: User Part Number: UPN; Tolerance: 0.1; alternate symbols: (R0603L); part number: RES_SM-4.42K,E026714,1/10W,0.1,R0603; tolerance: 0.1
R24 R65 R66 R82-R84 = RES: User Part Number: UPN; Tolerance: 1; alternate symbols: (R0603L); part number: RES_SM-100K,E017050,1/10W,1,R0603; tolerance: 1
R26 R112-R115 = RES: User Part Number: UPN; Tolerance: JUMPER; alternate symbols: (R2512H35); part number: RES_SM-0,E050944,N/A,JUMPER,R2512H35; tolerance: JUMPER
R27 R32-R36 R87-R91 = RES: User Part Number: UPN; Tolerance: N/A; alternate symbols: (R0805L); part number: RES_SM-0,E004449,1/8W,N/A,R0805; tolerance: N/A
R28 R29 R59 R60 = RES: User Part Number: UPN; Tolerance: 1; alternate symbols: (R0603L); part number: RES_SM-1MEG,E003682,1/10W,1,R0603; tolerance: 1
R30 R85 = RES: User Part Number: UPN; Tolerance: 1; alternate symbols: (R0603L); part number: RES_SM-11.3K,E027487,1/10W,1,R0603; tolerance: 1
R31 R86 = RES: User Part Number: UPN; Tolerance: 1; alternate symbols: (R0603L); part number: RES_SM-2.2,E017481,1/10W,1,R0603; tolerance: 1
R37 R40 R92 R95 = RES: User Part Number: UPN; Tolerance: 1; alternate symbols: (R0603L); part number: RES_SM-10,E003666,1/10W,1,R0603; tolerance: 1
R38 = RES: User Part Number: UPN; Tolerance: 0.1; alternate symbols: (R0603L); part number: RES_SM-499K,E041429,1/10W,0.1,R0603; tolerance: 0.1
R39 = RES: User Part Number: UPN; Tolerance: 0.1; alternate symbols: (R0603L); part number: RES_SM-26.1K,E054953,1/5W,0.1,R0603; tolerance: 0.1
R42 R97 = RES: User Part Number: UPN; Tolerance: 0.1; alternate symbols: (R0603L); part number: RES_SM-6.65K,E054954,1/10W,0.1,R0603; tolerance: 0.1
R43 R46 = RES: User Part Number: UPN; Tolerance: 1; alternate symbols: (R0603L); part number: RES_SM-6.81K,E026196,1/10W,1,R0603; tolerance: 1
R44 R49 = RES: User Part Number: UPN; Tolerance: 1; alternate symbols: (R0603L); part number: RES_SM-680,E038010,1/10W,1,R0603; tolerance: 1
R45 R50 R100 R105 = RES: User Part Number: UPN; Tolerance: JUMPER; alternate symbols: (R1206); part number: RES_SM-0,E004448,1/4W,JUMPER,R1206; tolerance: JUMPER
R51 R55 = RES: User Part Number: UPN; Tolerance: 1; alternate symbols: (R2512H35); part number: RES_SM-0.0008,E054056,2W,1,R2512H35; tolerance: 1
R57 R119 = RES: User Part Number: UPN; Tolerance: 1; alternate symbols: (R0603L); part number: RES_SM-10.7,E056168,1/10W,1,R0603; tolerance: 1
R62 R120 R121 = RES: User Part Number: UPN; Tolerance: 1; alternate symbols: (R0603L); part number: RES_SM-10K,E003671,1/10W,1,R0603; tolerance: 1
R64 R75 R93 = RES: User Part Number: UPN; Tolerance: 1; alternate symbols: (R0603L); part number: RES_SM-1.24MEG,E054955,1/10W,1,R0603; tolerance: 1
R67 = RES: User Part Number: UPN; Tolerance: 1; alternate symbols: (R0603L); part number: RES_SM-20K,E017927,1/10W,1,R0603; tolerance: 1
R68 = RES: User Part Number: UPN; Tolerance: 1; alternate symbols: (R0603L); part number: RES_SM-200K,E015343,1/10W,1,R0603; tolerance: 1
R69 = RES: User Part Number: UPN; Tolerance: 0.1; alternate symbols: (R0603L); part number: RES_SM-82.5K,E055033,1/10W,0.1,R0603; tolerance: 0.1
R73 = RES: User Part Number: UPN; Tolerance: 0.1; alternate symbols: (R0603L); part number: RES_SM-95.3K,E046238,1/10W,0.1,R0603; tolerance: 0.1
R76 = RES: User Part Number: UPN; Tolerance: 0.1; alternate symbols: (R0603L); part number: RES_SM-110K,E039871,1/10W,0.1,R0603; tolerance: 0.1
R77 = RES: User Part Number: UPN; Tolerance: 1; alternate symbols: (R0603L); part number: RES_SM-49.9K,E015342,1/10W,1,R0603; tolerance: 1
R81 = RES: User Part Number: UPN; Tolerance: 0.1; alternate symbols: (R0603L); part number: RES_SM-18.2K,E049212,1/10W,0.1,R0603; tolerance: 0.1
R94 = RES: User Part Number: UPN; Tolerance: 1; alternate symbols: (R0603L); part number: RES_SM-42.2K,E030956,1/10W,1,R0603; tolerance: 1
R98 R101 = RES: User Part Number: UPN; Tolerance: 1; alternate symbols: (R0603L); part number: RES_SM-7.32K,E024630,1/10W,1,R0603; tolerance: 1
R99 R104 = RES: User Part Number: UPN; Tolerance: 1; alternate symbols: (R0603L); part number: RES_SM-732,E047204,1/10W,1,R0603; tolerance: 1
R106 R110 = RES: User Part Number: UPN; Tolerance: 1; alternate symbols: (R2512H57); part number: RES_SM-0.002,E044963,3W,1,R2512H57; tolerance: 1
R117 = RES: User Part Number: UPN; Tolerance: 1; alternate symbols: (R0603L); part number: RES_SM-150K,E003672,1/10W,1,R0603; tolerance: 1
R118 = RES: User Part Number: UPN; Tolerance: 0.1; alternate symbols: (R0603L); part number: RES_SM-10K,E003965,1/10W,0.1,R0603; tolerance: 0.1
R122 R123 = RES: User Part Number: UPN; Tolerance: 1; alternate symbols: (R0603L); part number: RES_SM-2,E031412,1/10W,1,R0603; tolerance: 1
TP1 TP2 TP9 TP10 TP17 TP18 = CNTP1P: User Part Number: UPN; Tolerance: N/A; alternate symbols: (CNKEY5019); part number: CNTP1P_SM-5019,E021431,CNKEY5019; tolerance: N/A
TP3-TP8 TP11-TP16 = NCTESTPAD: Tolerance: N/A; User Part Number: UPN; alternate symbols: (TPC50D30); part number: NCTESTPAD_TH-TESTPAD,E007450,TPC50D30; tolerance: N/A
U1 U2 = ICLTC3871: User Part Number: UPN; Tolerance: N/A; alternate symbols: (LQFP48_7X7_PAD3_6X3_6); part number: ICLTC3871_SM-LTC3871ILXE#PBF,E033523,LQFP48_7X7_PAD3_6X3_6; tolerance: N/A

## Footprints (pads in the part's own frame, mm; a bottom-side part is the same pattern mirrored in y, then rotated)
C0603
  rect 0.762x0.889 smd: 1(-0.7,0) 2(0.7,0)
C0805
  rect 1.016x1.372 smd: 1(-0.803,0) 2(0.803,0)
C0805H53
  rect 1.295x1.6 smd: 1(-0.952,0) 2(0.952,0)
C1210H106
  rect 1.092x2.057 smd: 1(-1.646,0) 2(1.646,0)
C1210H110
  rect 1.372x2.794 smd: 1(-1.431,0) 2(1.431,0)
CNHIROSE-U_FL-R-SMT-1
  rect 0.991x1.041 smd: 1(0,-1.521)
  rect 1.041x2.21 smd: 2(-1.471,0) 3(1.471,0)
CNKEY5019
  rect 3.81x2.032 smd: 1(0,0)
CNPEMKFH-032
  round 6.858 hole 4.851: 1(0,0)
CNTHMHDR1X3L236W79H244
  rect 1.397x1.397 hole 0.889: 1(0,0)
  round 1.397 hole 0.889: 2(2,0) 3(4,0)
CPLSMSQ327H276
  rect 3.454x1.956 smd: N(3.35,0) P(-3.35,0)
CPLSMSQ327H461
  rect 3.81x2.032 smd: N(3.35,0) P(-3.35,0)
CPLSMSQ406H500
  rect 4.394x1.905 smd: N(4.347,0) P(-4.347,0)
L2815
  rect 6.35x5.283 smd: (0,7.722)
  rect 5.334x5.588 smd: 1(-5.075,-14.354) 2(5.075,-14.354)
LED0603
  rect 0.965x0.762 smd: A(0.8,0) C(-0.8,0)
LQFP48_7X7_PAD3_6X3_6
  rect 0.305x1.168 smd: 1(-2.75,-4.119) 2(-2.25,-4.119) 3(-1.75,-4.119) 4(-1.25,-4.119) 5(-0.75,-4.119) 6(-0.25,-4.119) 7(0.25,-4.119) 8(0.75,-4.119) 9(1.25,-4.119) 10(1.75,-4.119) 11(2.25,-4.119) 12(2.75,-4.119) 25(2.75,4.119) 26(2.25,4.119) 27(1.75,4.119) 28(1.25,4.119) 29(0.75,4.119) 30(0.25,4.119) 31(-0.25,4.119) 32(-0.75,4.119) 33(-1.25,4.119) 34(-1.75,4.119) 35(-2.25,4.119) 36(-2.75,4.119)
  rect 1.168x0.305 smd: 13(4.119,-2.75) 14(4.119,-2.25) 15(4.119,-1.75) 16(4.119,-1.25) 17(4.119,-0.75) 18(4.119,-0.25) 19(4.119,0.25) 20(4.119,0.75) 21(4.119,1.25) 22(4.119,1.75) 23(4.119,2.25) 24(4.119,2.75) 37(-4.119,2.75) 38(-4.119,2.25) 39(-4.119,1.75) 40(-4.119,1.25) 41(-4.119,0.75) 42(-4.119,0.25) 43(-4.119,-0.25) 44(-4.119,-0.75) 45(-4.119,-1.25) 46(-4.119,-1.75) 47(-4.119,-2.25) 48(-4.119,-2.75)
  rect 3.607x3.607 smd: PAD(0,0)
LSML1102W764H728
  rect 6.35x5.283 smd: (0,10.514)
  rect 5.334x5.588 smd: 1(-5.075,-11.56) 2(5.075,-11.56)
POWERDI123
  rect 0.889x1.397 smd: A(1.606,0)
  rect 2.21x1.397 smd: C(-0.945,0)
R0603
  rect 0.61x0.889 smd: 1(-0.75,0) 2(0.75,0)
R0805
  rect 0.838x1.295 smd: 1(-0.85,0) 2(0.85,0)
R1206
  rect 1.041x1.753 smd: 1(-1.5,0) 2(1.5,0)
R2512H35
  rect 2.108x3.988 smd: 1(-3.104,0) 2(3.104,0)
R2512H57
  rect 2.235x3.429 smd: 1(-2.693,0) 2(2.693,0)
R2726
  rect 2.438x0.889 smd: 1(-2.464,3.238) 3(2.464,3.238)
  rect 2.438x5.588 smd: 2(-2.464,-0.889) 4(2.464,-0.889)
SOD128
  rect 0.991x1.93 smd: A(2.21,0) C(-2.21,0)
SON8
  rect 0.66x1.194 smd: 1(-1.921,-2.828) 2(-0.64,-2.828) 3(0.64,-2.828) 4(1.921,-2.828)
  custom 1.175x1.175 smd: 5(2,3.171)
  round 0.127 smd: 6(0.678,3.211) 7(-0.68,3.236) 8(-2.002,3.223)
SOT23-M3
  rect 0.787x0.889 smd: 1(-0.94,-1.003) 2(0.94,-1.003) 3(0,1.003)
SOT23_B
  rect 0.61x1.041 smd: 1(-0.958,-1.15) 2(0.958,-1.15) 3(0,1.15)
TO252-3
  rect 1.397x2.286 smd: 1(-2.29,-4.191) 2(2.28,-4.191)
  rect 5.69x6.172 smd: 3(0,2.248)
TPC50D30
  round 1.27 hole 0.762: 1(0,0)
unnamed#2
  round 4.445 hole 3.175 unplated: (0,0)

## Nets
GND_SIGNAL: C1.2(N2) C2.2(N2) C3.2(N2) C4.2(N2) C5.1 C6.1 C7.1 C8.2(N2) C9.1 C12.2(N2) C13.N(N2) C14.N(N2) C15.N(N2) C16.2(N2) C17.N(N2) C18.1 C19.2(N2) C20.1 C21.1 C22.1 C23.1 C24.1 C28.N(N2) C30.N(N2) C31.N(N2) C32.N(N2) C33.N(N2) C34.N(N2) C35.N(N2) C36.1 C37.1 C38.N(N2) C39.1 C40.1 C41.1 C42.1 C43.N(N2) C44.1 C57.N(N2) C58.N(N2) C59.N(N2) C61.N(N2) C62.1 C64.1 C72.N(N2) C73.N(N2) C75.N(N2) C76.N(N2) C78.P C79.P C80.1 C81.P C82.1 C83.P C84.2(N2) C85.P C86.2(N2) C88.P C89.2(N2) C90.2(N2) C92.1 C93.2(N2) C95.2(N2) C96.2(N2) C97.N(N2) C98.P C99.N(N2) C100.P C102.N(N2) C104.P C105.N(N2) C106.N(N2) C107.P C108.N(N2) C109.P C110.N(N2) C111.P C112.N(N2) C113.N(N2) C114.1 C115.1 C116.1 C117.2(N2) D5.C D6.C J1.2 J1.3(SH2) J2.2 J2.3(SH2) J3.2 J3.3(SH2) P3.1(N1) P4.1(N1) P5.3(N3) P7.1(N1) P9.1(N1) P12.1(N1) P14.1(N1) Q1.2(S) Q4.2(S) Q6.1 Q6.2 Q6.3(S3) Q8.1 Q8.2 Q8.3(S3) Q10.1 Q10.2 Q10.3(S3) Q12.1 Q12.2 Q12.3(S3) Q13.2(S) Q16.2(S) R3.2 R4.4(N4) R9.1 R10.2(N2) R12.1 R14.1 R16.2(N2) R18.2(N2) R19.1 R21.2(N2) R23.2(N2) R29.2(N2) R39.2(N2) R42.2(N2) R64.1 R84.2(N2) R91.2(N2) R95.2(N2) R106.1 R109.2(N2) R110.2(N2) R111.2(N2) R116.2(N2) R118.2(N2) R121.2(N2) TP2.1(N1) TP10.1(N1) TP17.1(N1) U1.7 U1.26 U1.28 U1.35 U1.PAD
V5_N: C52.1 R61.2(N2) R68.1 R70.1 R72.1 R78.1 R82.1 U2.6 U2.16
V5_P: C8.1 R7.2(N2) R11.1 R13.1 R15.1 R22.1 R24.1 R25.1 R120.1 U1.6
VIN: DS1.A(P) DS2.A(P) P1.1(N1) P2.1(N1) R28.1 R59.1 R65.1 R83.1 R112.1 R113.1 R117.1 TP1.1(N1)
DRVCC_N: C51.2(N2) D3.A(P) D4.A(P) U2.29
DRVCC_P: C7.2(N2) D1.A(P) D2.A(P) U1.29
FAULT_N: Q15.1 R82.2(N2) U2.19
PGATE: R27.2(N2) U1.33
RUN_N: R66.2(N2) R67.1 U2.18
RUN_P: P5.2 R117.2(N2) R118.1 U1.18
UNNAMED_7_CAP_I29_N2: C5.2(N2) U1.11
UNNAMED_7_CAP_I48_N1: C4.1 R8.2(N2)
UNNAMED_7_CAP_I49_N1: C3.1 R8.1 U1.3
UNNAMED_7_CAP_I67_N1: C2.1 R5.2(N2)
UNNAMED_7_CAP_I68_N1: C1.1 R5.1 U1.4
UNNAMED_7_CAP_I69_N2: C6.2(N2) U1.1
UNNAMED_7_CAP_I83_N2: C9.2(N2) R31.1 U1.31(VHIGH)
UNNAMED_7_CAP_I87_N1: C11.1 L1.2(N2) Q5.1 Q5.2 Q5.3(S3) Q6.5 Q6.6 Q6.7 Q6.8 Q9.1 Q9.2 Q9.3(S3) Q10.5 Q10.6 Q10.7 Q10.8 R43.1 R45.1 TP3.1(N1) U1.23
UNNAMED_7_CAP_I87_N2: C11.2(N2) D2.C R57.2(N2)
UNNAMED_7_CAP_I93_N1: C10.1 L2.1 Q7.1 Q7.2 Q7.3(S3) Q8.5 Q8.6 Q8.7 Q8.8 Q11.1 Q11.2 Q11.3(S3) Q12.5 Q12.6 Q12.7 Q12.8 R46.1 R50.1 TP6.1(N1) U1.38
UNNAMED_7_CAP_I93_N2: C10.2(N2) D1.C R119.2(N2)
UNNAMED_7_CAP_I127_N1: C12.1 R36.1 U1.27
UNNAMED_7_CAP_I149_N1: C26.1 C29.1 R2.1 R49.1 R56.1 U1.47
UNNAMED_7_CAP_I149_N2: C26.2(N2) R46.2(N2) R49.2(N2) U1.48
UNNAMED_7_CAP_I199_N1: C25.1 C27.1 R1.3 R44.1 R54.1 U1.14
UNNAMED_7_CAP_I199_N2: C27.2(N2) R45.2(N2) R47.1 U1.15
UNNAMED_7_CAP_I202_N2: C25.2(N2) R43.2(N2) R44.2(N2) U1.13
UNNAMED_7_DIOLED_I185_N: DS1.C R30.1
UNNAMED_7_ICLTC3871_I31_BG1: R33.1 U1.36
UNNAMED_7_ICLTC3871_I31_BG2: R35.1 U1.25
UNNAMED_7_ICLTC3871_I31_BOOST1: R119.1 U1.37
UNNAMED_7_ICLTC3871_I31_BOOST2: R57.1 U1.24
UNNAMED_7_ICLTC3871_I31_BUCK: R25.2(N2) R116.1 U1.16
UNNAMED_7_ICLTC3871_I31_DRVSET: R22.2(N2) R23.1 U1.20
UNNAMED_7_ICLTC3871_I31_FAULTN: Q1.1 R24.2(N2) U1.19
UNNAMED_7_ICLTC3871_I31_FREQ: R19.2(N2) U1.43
UNNAMED_7_ICLTC3871_I31_ILIM: R7.1 R9.2(N2) U1.17
UNNAMED_7_ICLTC3871_I31_MODE: R15.2(N2) R16.1 U1.44
UNNAMED_7_ICLTC3871_I31_OVHIGH: R20.1 R21.1 U1.8
UNNAMED_7_ICLTC3871_I31_OVLOW: R6.2(N2) R10.1 U1.10
UNNAMED_7_ICLTC3871_I31_PHSMD: R13.2(N2) R14.2(N2) U1.45
UNNAMED_7_ICLTC3871_I31_SETCUR: R11.2(N2) R12.2(N2) U1.12
UNNAMED_7_ICLTC3871_I31_SNSD1: C29.2(N2) R50.2(N2) R52.1 U1.46
UNNAMED_7_ICLTC3871_I31_TG1: R32.1 U1.39
UNNAMED_7_ICLTC3871_I31_TG2: R34.1 U1.22
UNNAMED_7_ICLTC3871_I31_UVHIGH: R17.1 R18.1 U1.9
UNNAMED_7_IND_I144_N2: L2.2(N2) R2.4(N4) R53.2(N2) R55.1
UNNAMED_7_IND_I265_N1: L1.1 R1.2 R48.2(N2) R51.1
UNNAMED_7_NCTESTPAD_I102_N1: Q8.4 Q12.4 R33.2(N2) TP8.1(N1)
UNNAMED_7_NCTESTPAD_I215_N1: Q5.4 Q9.4 R34.2(N2) TP4.1(N1)
UNNAMED_7_NCTESTPAD_I219_N1: Q6.4 Q10.4 R35.2(N2) TP5.1(N1)
UNNAMED_7_RES_I45_N2: Q7.4 Q11.4 R32.2(N2) TP7.1(N1)
UNNAMED_7_RES_I133_N1: R37.2(N2) R38.1
UNNAMED_7_RES_I157_N1: R40.1 R41.1
UNNAMED_7_RES_I157_N2: R41.2(N2) R42.1 U1.2
UNNAMED_7_RES_I183_N2: Q4.3 R30.2(N2)
UNNAMED_7_RES_I188_N1: Q2.1 Q3.1 R27.1
UNNAMED_7_RES_I194_N1: R2.3 R52.2(N2) R53.1
UNNAMED_7_RES_I205_N2: R1.1 R47.2(N2) R48.1
UNNAMED_7_TRAN2N7002_I177_D: Q1.3 Q4.1 R28.2(N2) R29.1
UNNAMED_9_CAP_I9_N1: C45.1 R58.1 U2.4
UNNAMED_9_CAP_I11_N1: C46.1 R58.2(N2)
UNNAMED_9_CAP_I13_N1: C47.1 R62.1 U2.3
UNNAMED_9_CAP_I15_N1: C48.1 R62.2(N2)
UNNAMED_9_CAP_I43_N2: C49.2(N2) U2.11
UNNAMED_9_CAP_I53_N2: C50.2(N2) U2.1
UNNAMED_9_CAP_I61_N2: C53.2(N2) R86.1 U2.31(VHIGH)
UNNAMED_9_CAP_I91_N1: C55.1 L3.2(N2) Q17.1 Q17.2 Q17.3(S3) Q18.5 Q18.6 Q18.7 Q18.8 Q21.1 Q21.2 Q21.3(S3) Q22.5 Q22.6 Q22.7 Q22.8 R98.1 R100.1 TP11.1(N1) U2.23
UNNAMED_9_CAP_I91_N2: C55.2(N2) D4.C R122.2(N2)
UNNAMED_9_CAP_I93_N1: C54.1 L4.1 Q19.1 Q19.2 Q19.3(S3) Q20.5 Q20.6 Q20.7 Q20.8 Q23.1 Q23.2 Q23.3(S3) Q24.5 Q24.6 Q24.7 Q24.8 R101.1 R105.1 TP14.1(N1) U2.38
UNNAMED_9_CAP_I93_N2: C54.2(N2) D3.C R123.2(N2)
UNNAMED_9_CAP_I95_N1: C56.1 R91.1 U2.27
UNNAMED_9_CAP_I126_N1: C69.1 C74.1 R3.1 R99.1 R109.1 U2.14
UNNAMED_9_CAP_I126_N2: C69.2(N2) R98.2(N2) R99.2(N2) U2.13
UNNAMED_9_CAP_I130_N2: C74.2(N2) R100.2(N2) R102.1 U2.15
UNNAMED_9_CAP_I138_N1: C71.1 C77.1 R4.3 R104.1 R111.1 U2.47
UNNAMED_9_CAP_I138_N2: C71.2(N2) R101.2(N2) R104.2(N2) U2.48
UNNAMED_9_CAP_I143_N2: C77.2(N2) R105.2(N2) R107.1 U2.46
UNNAMED_9_DIOLED_I242_N: DS2.C R85.1
UNNAMED_9_ICLTC3871_I21_BG1: R88.1 U2.36
UNNAMED_9_ICLTC3871_I21_BG2: R90.1 U2.25
UNNAMED_9_ICLTC3871_I21_BOOST1: R123.1 U2.37
UNNAMED_9_ICLTC3871_I21_BOOST2: R122.1 U2.24
UNNAMED_9_ICLTC3871_I21_DRVSET: R78.2(N2) R79.1 U2.20
UNNAMED_9_ICLTC3871_I21_FREQ: R77.1 U2.43
UNNAMED_9_ICLTC3871_I21_ILIM: R61.1 R63.2(N2) U2.17
UNNAMED_9_ICLTC3871_I21_MODE: R72.2(N2) R74.1 U2.44
UNNAMED_9_ICLTC3871_I21_OVHIGH: R80.1 R81.1 U2.8
UNNAMED_9_ICLTC3871_I21_OVLOW: R64.2(N2) R69.1 U2.10
UNNAMED_9_ICLTC3871_I21_PHSMD: R70.2(N2) R71.2(N2) U2.45
UNNAMED_9_ICLTC3871_I21_SETCUR: R68.2(N2) R73.1 U2.12
UNNAMED_9_ICLTC3871_I21_TG1: R87.1 U2.39
UNNAMED_9_ICLTC3871_I21_TG2: R89.1 U2.22
UNNAMED_9_ICLTC3871_I21_UVHIGH: R75.1 R76.1 U2.9
UNNAMED_9_ICLTC3871_I21_VFBLOW: R96.2(N2) R97.1 U2.2
UNNAMED_9_IND_I114_N1: L3.1 R3.4(N4) R103.2(N2) R106.2(N2)
UNNAMED_9_IND_I133_N2: L4.2(N2) R4.2 R108.2(N2) R110.1
UNNAMED_9_NCTESTPAD_I80_N1: Q18.4 Q22.4 R90.2(N2) TP13.1(N1)
UNNAMED_9_NCTESTPAD_I83_N1: Q17.4 Q21.4 R89.2(N2) TP12.1(N1)
UNNAMED_9_NCTESTPAD_I104_N1: Q20.4 Q24.4 R88.2(N2) TP16.1(N1)
UNNAMED_9_NCTESTPAD_I109_N1: Q19.4 Q23.4 R87.2(N2) TP15.1(N1)
UNNAMED_9_RES_I102_N1: R95.1 R96.1
UNNAMED_9_RES_I115_N1: R3.3 R102.2(N2) R103.1
UNNAMED_9_RES_I134_N1: R4.1 R107.2(N2) R108.1
UNNAMED_9_RES_I145_N1: R92.2(N2) R93.1
UNNAMED_9_RES_I232_N1: Q14.1 R59.2(N2) R60.1
UNNAMED_9_RES_I232_N2: Q13.3 R60.2(N2)
UNNAMED_9_RES_I235_N1: Q14.3 R66.1
UNNAMED_9_RES_I236_N2: Q14.2(S) R65.2(N2)
UNNAMED_9_RES_I239_N1: Q15.3 Q16.1 R83.2(N2) R84.1
UNNAMED_9_RES_I244_N2: Q16.3 R85.2(N2)
UNNAMED_9_RES_I291_N2: Q13.1 R120.2(N2) R121.1
VFBHIGH_N: R93.2(N2) R94.1 U2.5
VFBHIGH_P: R38.2(N2) R39.1 U1.5
VHIGH: C43.P C92.2(N2) C113.P C114.2(N2) C115.2(N2) J1.1 Q2.3 Q3.3 R17.2(N2) R20.2(N2) R26.1 R112.2(N2) R115.1
VHIGH_P: C13.P C14.P C15.P C16.1 C17.P C18.2(N2) C19.1 C20.2(N2) C21.2(N2) C22.2(N2) C23.2(N2) C24.2(N2) C97.P C99.P C102.P C105.P C106.P C108.P C110.P C112.P Q2.2(S) Q3.2(S) Q5.5 Q5.6 Q5.7 Q5.8 Q7.5 Q7.6 Q7.7 Q7.8 Q9.5 Q9.6 Q9.7 Q9.8 Q11.5 Q11.6 Q11.7 Q11.8 R26.2(N2) R31.2(N2) R37.1
VLOW_P: C28.P C30.P C31.P C32.P C33.P C34.P C35.P C36.2(N2) C37.2(N2) C38.P C39.2(N2) C40.2(N2) C41.2(N2) C42.2(N2) C44.2(N2) C57.P C58.P C59.P C60.1 C61.P C62.2(N2) C63.1 C64.2(N2) C65.2(N2) C66.P C67.2(N2) C68.2(N2) C70.2(N2) C72.P C73.P C75.P C76.P C80.2(N2) C82.2(N2) C87.P C91.2(N2) C94.2(N2) C101.P C103.P C116.2(N2) J2.1 Q17.5 Q17.6 Q17.7 Q17.8 Q19.5 Q19.6 Q19.7 Q19.8 Q21.5 Q21.6 Q21.7 Q21.8 Q23.5 Q23.6 Q23.7 Q23.8 R1.4(N4) R2.2 R6.1 R36.2(N2) R40.2(N2) R51.2(N2) R54.2(N2) R55.2(N2) R56.2(N2) R75.2(N2) R80.2(N2) R86.2(N2) R92.1 R113.2(N2) R114.1
VNEG: C45.2(N2) C46.2(N2) C47.2(N2) C48.2(N2) C49.1 C50.1 C51.1 C52.2(N2) C53.1 C56.2(N2) C60.2(N2) C63.2(N2) C65.1 C66.N(N2) C67.1 C68.1 C70.1 C78.N(N2) C79.N(N2) C81.N(N2) C83.N(N2) C84.1 C85.N(N2) C86.1 C87.N(N2) C88.N(N2) C89.1 C90.1 C91.1 C93.1 C94.1 C95.1 C96.1 C98.N(N2) C100.N(N2) C101.N(N2) C103.N(N2) C104.N(N2) C107.N(N2) C109.N(N2) C111.N(N2) C117.1 D5.A(P) D6.A(P) J3.1 P13.1(N1) P15.1(N1) Q15.2(S) Q18.1 Q18.2 Q18.3(S3) Q20.1 Q20.2 Q20.3(S3) Q22.1 Q22.2 Q22.3(S3) Q24.1 Q24.2 Q24.3(S3) R63.1 R67.2(N2) R69.2(N2) R71.1 R73.2(N2) R74.2(N2) R76.2(N2) R77.2(N2) R79.2(N2) R81.2(N2) R94.2(N2) R97.2(N2) TP18.1(N1) U2.7 U2.26 U2.28 U2.35 U2.PAD
VPOS: P6.1(N1) P8.1(N1) R114.2(N2) R115.2(N2) TP9.1(N1)

Pads without a net: P5 1; U1 21 30 32 34 40 41 42; U2 21 30 32 33 34 40 41 42

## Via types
v1: diameter 1.016, hole 0.508, TOP to BOTTOM, 1258 vias
v2: diameter 0.508, hole 0.254, TOP to BOTTOM, 222 vias

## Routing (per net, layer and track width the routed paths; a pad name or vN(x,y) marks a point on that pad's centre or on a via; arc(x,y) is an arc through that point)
GND_SIGNAL: length 202.6
  TOP w0.2: J1.3 v2(160.08,160.09) ; C23.1 v1(109.92,158.49) ; R4.4 v2(114.66,57.5) ; C18.1 v1(99.25,158.49) ; J1.2 v2(163.02,160.09) ; C22.1 v1(106.36,158.49) ; C20.1 v1(102.81,158.49) ; R3.2 v2(94.51,57.5)
  TOP w0.508: C16.2 v1(96.87,159.52) ; C19.2 v1(112.3,159.52)
  TOP w0.635: 159.58,43.29 C117.2 158.81,42.34 ; 159.14,40.94 C96.2
  TOP w0.65: C21.1 v1(95.67,159.52) ; C24.1 v1(113.5,159.52)
  TOP w0.66: C89.2 v1(104.63,66.53) ; C93.2 v1(104.57,71.35) ; Q8.3 v1(113.02,153.27) ; Q12.3 v1(113.02,147.33) ; Q6.3 v1(96.02,148.61) ; Q6.1 v1(96.02,146.05) ; Q8.2 v1(113.02,154.55) ; J3.2 v1(159.71,47.4) ; C86.2 v1(104.63,70.07) ; Q10.2 v1(96.02,153.27) ; Q8.1 v1(113.02,155.83) ; Q10.1 v1(96.02,151.99) ; J3.3 v1(162.65,47.4) ; Q12.1 v1(113.02,149.89) ; C95.2 v1(104.57,74.89) ; Q12.2 v1(113.02,148.61) ; Q10.3 v1(96.02,154.55) ; Q6.2 v1(96.02,147.33) ; C84.2 v1(104.63,73.61) ; C90.2 v1(104.57,67.81)
  L2_PWR w0.635: P5.3 38.81,123.18 ; P5.3 38.81,124.81 ; P5.3 37.18,123.18 ; P5.3 37.18,124.81
  L3_SIG w0.635: P5.3 38.81,124.81 ; P5.3 37.18,124.81 ; P5.3 38.81,123.18 ; P5.3 37.18,123.18
  L4_SIG w0.508: v1(148.94,43.4) 147.9,42.36 125.52,42.36 117.24,34.08 117.24,31.28 115.61,29.66 99.5,29.66 v2(98.03,28.19) ; v1(152.39,43.4) 149.45,40.45 125.76,40.45 v2(118.61,33.31)
  L4_SIG w0.635: 37.18,123.18 P5.3 ; P5.3 38.81,123.18 ; P5.3 37.18,124.81 ; P5.3 38.81,124.81
  L5_GND w0.635: 37.18,123.18 P5.3 ; P5.3 38.81,123.18 ; P5.3 37.18,124.81 ; P5.3 38.81,124.81
  BOTTOM w0.2: R84.2 v2(43.69,69.1) ; R91.2 v2(101.54,54.87) ; 103.67,140.37 v2(103.29,140.37) ; 103.67,140.37 v2(104.06,140.37) ; 103.67,140.37 C7.1 ; R111.2 114.66,57.49 v2(114.66,57.5) ; R109.2 94.51,55.62 v2(94.51,57.5) ; Q16.2 v2(47.28,69.31) ; U1.26 v2(102.18,133.06) ; U1.28 v2(103.18,133.06) ; U1.35 v2(106.68,133.06) ; U1.7 104.18,125.22 ; Q13.2 v2(45.34,56.89)
  BOTTOM w0.3: C8.2 104.18,123.15 104.18,125.22
  BOTTOM w0.508: R18.2 v2(100.27,119.12) ; C4.2 v2(113.01,118.65) ; R19.1 v2(119.23,133) ; C2.2 v2(110.61,118.65) ; R118.2 v2(36.02,123.33) ; R42.2 v2(114.11,117.86) ; R16.2 v2(122.31,129.84) ; R64.1 v2(98.03,28.19) ; Q4.2 v2(52.2,143.02) ; R39.2 v2(108.31,120.36) ; C1.2 v2(110.61,120.35) ; R23.2 v2(86.61,133) ; C3.2 v2(113.01,120.35) ; R9.1 v2(86.61,129.84) ; R12.1 v2(95.53,119.19) ; Q1.2 v2(52.18,149.94) ; R95.2 v2(118.61,33.31) ; C9.1 v2(105.83,139.07) ; R29.2 v2(52.81,145.54) ; R116.2 v2(86.61,126.94) ; R21.2 v2(101.85,119.12) ; C5.1 v2(97.11,119.17) ; R14.1 v2(122.31,131.42) ; R10.2 v2(98.69,119.12) ; C8.2 v2(103.48,121.19) ; C6.1 v2(110.45,125.5) ; C12.2 v2(101.51,139.07)
  BOTTOM w0.635: 44.81,51.84 R121.2 ; R121.2 44.81,52.98 ; R121.2 45.51,52.41 ; R121.2 44.1,52.41
  vias: v1(6.35,77.47) v1(6.35,67.31) v1(6.35,57.15) v1(6.35,46.99) v1(6.35,36.83) v1(6.35,26.67) v1(6.35,16.51) v1(11.43,72.39) v1(11.43,62.23) v1(11.43,52.07) v1(11.43,41.91) v1(11.43,31.75) v1(11.43,21.59) v1(11.43,11.43) v1(16.51,77.47) v1(16.51,67.31) v1(16.51,57.15) v1(16.51,46.99) v1(16.51,36.83) v1(16.51,26.67) v1(16.51,16.51) v1(16.51,6.35) v1(18.22,75.15) v1(18.22,49.78) v1(19.85,79.01) v1(19.85,71.29) v1(19.85,53.64) v1(19.85,45.92) v1(21.59,62.23) v1(21.59,41.91) v1(21.59,31.75) v1(21.59,21.59) v1(21.59,11.43) v1(23.71,80.64) v1(23.71,69.65) v1(23.71,55.27) v1(23.71,44.28) v1(26.67,67.31) v1(26.67,57.15) v1(26.67,36.83) v1(26.67,26.67) v1(26.67,16.51) v1(26.67,6.35) v1(27.57,79.01) v1(27.57,71.29) v1(27.57,53.64) v1(27.57,45.92) v1(29.2,75.15) v1(29.2,49.78) v1(31.75,62.23) v1(31.75,52.07) v1(31.75,41.91) v1(31.75,31.75) v1(31.75,21.59) v1(31.75,11.43) v1(36.83,77.47) v1(36.83,57.15) v1(36.83,46.99) v1(36.83,36.83) v1(36.83,26.67) v1(36.83,16.51) v1(36.83,6.35) v1(41.91,52.07) v1(41.91,41.91) v1(41.91,31.75) v1(41.91,21.59) v1(41.91,11.43) v1(46.99,77.47) v1(46.99,36.83) v1(46.99,26.67) v1(46.99,16.51) v1(46.99,6.35) v1(50.08,154.61) v1(50.08,134.29) v1(50.08,124.13) v1(50.08,113.97) v1(52.07,21.59) v1(52.07,11.43) v1(55.16,159.69) v1(55.16,149.53) v1(55.16,139.37) v1(55.16,129.21) v1(55.16,119.05) v1(56.77,47.21) v1(56.77,45.94) v1(56.77,44.67) v1(56.77,43.4) v1(57.15,67.31) v1(57.15,57.15) v1(60.24,154.61) v1(60.24,134.29) v1(60.24,124.13) v1(60.24,113.97) v1(60.23,47.21) v1(60.23,45.94) v1(60.23,44.67) v1(60.23,43.4) v1(62.23,72.39) v1(62.23,52.07) v1(64.14,99.2) v1(64.14,97.93) v1(64.14,96.66) v1(64.14,95.39) v1(65.32,159.69) v1(65.32,149.53) v1(65.32,129.21) v1(65.32,119.05) v1(67.31,77.47) v1(67.31,67.31) v1(67.31,57.15) v1(67.59,99.2) v1(67.59,97.93) v1(67.59,96.66) v1(67.59,95.39) v1(67.84,47.21) v1(67.84,45.94) v1(67.84,44.67) v1(67.84,43.4) v1(70.4,154.61) v1(70.4,144.45) v1(71.29,47.21) v1(71.29,45.94) v1(71.29,44.67) v1(71.29,43.4) v1(72.39,72.39) v1(72.39,62.23) v1(72.39,52.07) v1(75.21,184.32) v1(75.21,183.05) v1(75.21,181.78) v1(75.21,180.51) v1(75.2,99.2) v1(75.2,97.93) v1(75.2,96.66) v1(75.2,95.39) v1(75.48,149.53) v1(78.67,184.32) v1(78.67,183.05) v1(78.67,181.78) v1(78.67,180.51) v1(78.66,99.2) v1(78.66,97.93) v1(78.66,96.66) v1(78.66,95.39) v1(78.9,47.21) v1(78.9,45.94) v1(78.9,44.67) v1(78.9,43.4) v1(82.35,47.21) v1(82.35,45.94) v1(82.35,44.67) v1(82.35,43.4) v1(86.26,184.32) v1(86.26,183.05) v1(86.26,181.78) v1(86.26,180.51) v1(86.26,99.2) v1(86.26,97.93) v1(86.26,96.66) v1(86.26,95.39) v1(89.72,184.32) v1(89.72,183.05) v1(89.72,181.78) v1(89.72,180.51) v1(89.72,99.2) v1(89.72,97.93) v1(89.72,96.66) v1(89.72,95.39) v1(97.31,184.29) v1(97.31,183.02) v1(97.31,181.75) v1(97.31,180.48) v1(97.33,99.2) v1(97.33,97.93) v1(97.33,96.66) v1(97.33,95.39) v1(99.25,77.69) v1(100.77,184.29) v1(100.77,183.02) v1(100.77,181.75) v1(100.77,180.48) v1(100.78,99.2) v1(100.78,97.93) v1(100.78,96.66) v1(100.78,95.39) v1(102.81,77.69) v1(103.31,62.32) v1(103.33,59.79) v1(103.33,57.25) v1(104.58,63.59) v1(104.58,61.05) v1(104.6,58.52) v1(105.85,62.32) v1(105.87,59.79) v1(105.87,57.25) v1(106.36,77.69) v1(108.34,184.29) v1(108.34,183.02) v1(108.34,181.75) v1(108.34,180.48) v1(108.39,99.2) v1(108.39,97.93) v1(108.39,96.66) v1(108.39,95.39) v1(109.92,77.69) v1(111.79,184.29) v1(111.79,183.02) v1(111.79,181.75) v1(111.79,180.48) v1(111.84,99.2) v1(111.84,97.93) v1(111.84,96.66) v1(111.84,95.39) v1(119.44,184.32) v1(119.44,183.05) v1(119.44,181.78) v1(119.44,180.51) v1(119.45,99.2) v1(119.45,97.93) v1(119.45,96.66) v1(119.45,95.39) v1(122.89,184.32) v1(122.89,183.05) v1(122.89,181.78) v1(122.89,180.51) v1(122.9,99.2) v1(122.9,97.93) v1(122.9,96.66) v1(122.9,95.39) v1(126.82,47.21) v1(126.82,45.94) v1(126.82,44.67) v1(126.82,43.4) v1(130.27,47.21) v1(130.27,45.94) v1(130.27,44.67) v1(130.27,43.4) v1(130.51,184.32) v1(130.51,183.05) v1(130.51,181.78) v1(130.51,180.51) v1(130.51,99.2) v1(130.51,97.93) v1(130.51,96.66) v1(130.51,95.39) v1(133.96,184.32) v1(133.96,183.05) v1(133.96,181.78) v1(133.96,180.51) v1(133.97,99.2) v1(133.97,97.93) v1(133.97,96.66) v1(133.97,95.39) v1(137.5,154.61) v1(137.5,144.45) v1(137.88,47.21) v1(137.88,45.94) v1(137.88,44.67) v1(137.88,43.4) v1(138.43,67.31) v1(138.43,57.15) v1(141.33,47.21) v1(141.33,45.94) v1(141.33,44.67) v1(141.33,43.4) v1(141.57,99.2) v1(141.57,97.93) v1(141.57,96.66) v1(141.57,95.39) v1(142.58,159.69) v1(142.58,149.53) v1(142.58,139.37) v1(142.58,119.05) v1(143.51,72.39) v1(143.51,52.07) v1(145.03,99.2) v1(145.03,97.93) v1(145.03,96.66) v1(145.03,95.39) v1(146.82,162.6) v1(146.82,161.33) v1(146.82,160.06) v1(146.82,158.79) v1(147.66,154.61) v1(147.66,124.13) v1(147.66,113.97) v1(148.59,67.31) v1(148.59,57.15) v1(148.94,47.21) v1(148.94,45.94) v1(148.94,44.67) v1(150.27,162.6) v1(150.27,161.33) v1(150.27,160.06) v1(150.27,158.79) v1(152.39,47.21) v1(152.39,45.94) v1(152.39,44.67) v1(152.74,159.69) v1(152.74,149.53) v1(152.74,129.21) v1(152.74,119.05) v1(153.67,72.39) v1(153.67,62.23) v1(153.67,52.07) v1(154.79,161.9) v1(156.06,161.9) v1(156.62,111.68) v1(157.33,161.9) v1(157.82,134.29) v1(157.82,124.13) v1(157.82,113.97) v1(158.01,112.04) v1(158.34,42.32) v1(158.5,163.07) v1(158.65,40.97) v1(158.75,77.47) v1(158.75,67.31) v1(158.75,57.15) v1(159.74,112.65) v1(160.39,51.1) v1(160.39,49.83) v1(160.39,48.56) v1(160.86,158.69) v1(160.86,157.42) v1(160.86,156.15) v1(161.49,52.47) v1(161.96,154.79) v1(162.66,112.67) v1(162.76,52.47) v1(162.9,149.53) v1(162.9,139.37) v1(162.9,129.21) v1(163.23,154.79) v1(179.98,189.48) v1(179.98,164.08) v1(179.98,37.14) v1(180.02,11.67) v1(181.61,193.34) v1(181.61,185.62) v1(181.61,167.94) v1(181.61,160.22) v1(181.61,41) v1(181.61,33.28) v1(181.65,15.53) v1(181.65,7.81) v1(185.47,194.98) v1(185.47,183.99) v1(185.47,169.58) v1(185.47,158.59) v1(185.47,42.63) v1(185.47,31.65) v1(185.51,17.17) v1(185.51,6.18) v1(189.33,193.34) v1(189.33,185.62) v1(189.33,167.94) v1(189.33,160.22) v1(189.33,41) v1(189.33,33.28) v1(189.37,15.53) v1(189.37,7.81) v1(190.96,189.48) v1(190.96,164.08) v1(190.96,37.14) v1(191,11.67) v2(103.16,131.25) v2(103.16,129.98) v2(103.16,128.71) v2(103.8,130.61) v2(103.8,129.34) v2(104.43,131.25) v2(104.43,129.98) v2(104.43,128.71) v2(105.07,130.61) v2(105.07,129.34) v2(105.7,131.25) v2(105.7,129.98) v2(105.7,128.71)
